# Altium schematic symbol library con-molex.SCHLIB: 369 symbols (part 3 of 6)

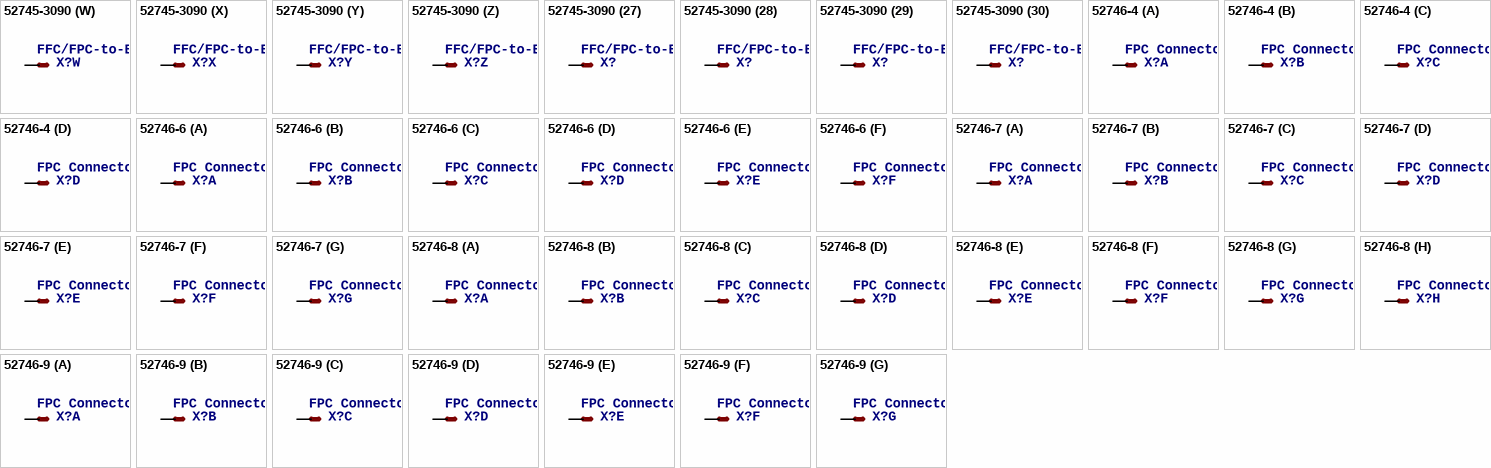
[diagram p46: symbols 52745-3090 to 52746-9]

## 52745-3090
designator X?, comment FFC/FPC-to-Board  0.50mm (.020") SMT Top Contact   Right Angle, ZIF, Style Receptacle 52745 / 52435 Source: http://www.molex.com/product/ffc/52745.html
footprint 52745-3090
part A pins: 1 S
part B pins: 2 S
part C pins: 3 S
part D pins: 4 S
part E pins: 5 S
part F pins: 6 S
part G pins: 7 S
part H pins: 8 S
part I pins: 9 S
part J pins: 10 S
part K pins: 11 S
part L pins: 12 S
part M pins: 13 S
part N pins: 14 S
part O pins: 15 S
part P pins: 16 S
part Q pins: 17 S
part R pins: 18 S
part S pins: 19 S
part T pins: 20 S
part U pins: 21 S
part V pins: 22 S
part W pins: 23 S
part X pins: 24 S
part Y pins: 25 S
part Z pins: 26 S
part 27 pins: 27 S
part 28 pins: 28 S
part 29 pins: 29 S
part 30 pins: 30 S

## 52746-4
designator X?, comment FPC Connector ZIF for SMT 0.5mm   Source: http://www.farnell.com/datasheets/73044.pdf [DWG. NO. (Sheet 1 OF 2) SD-52746-**17]
MPN: 52746-442
footprint 52746-4
part A pins: 1 S
part B pins: 2 S
part C pins: 3 S
part D pins: 4 S

## 52746-6
designator X?, comment FPC Connector ZIF for SMT 0.5mm   Source: http://www.farnell.com/datasheets/73044.pdf [DWG. NO. (Sheet 1 OF 2) SD-52746-**17]
footprint 52746-6
part A pins: 1 S
part B pins: 2 S
part C pins: 3 S
part D pins: 4 S
part E pins: 5 S
part F pins: 6 S

## 52746-7
designator X?, comment FPC Connector ZIF for SMT 0.5mm   Source: http://www.farnell.com/datasheets/73044.pdf [DWG. NO. (Sheet 1 OF 2) SD-52746-**17]
footprint 52746-7
part A pins: 1 S
part B pins: 2 S
part C pins: 3 S
part D pins: 4 S
part E pins: 5 S
part F pins: 6 S
part G pins: 7 S

## 52746-8
designator X?, comment FPC Connector ZIF for SMT 0.5mm   Source: http://www.farnell.com/datasheets/73044.pdf [DWG. NO. (Sheet 1 OF 2) SD-52746-**17]
footprint 52746-8
part A pins: 1 S
part B pins: 2 S
part C pins: 3 S
part D pins: 4 S
part E pins: 5 S
part F pins: 6 S
part G pins: 7 S
part H pins: 8 S

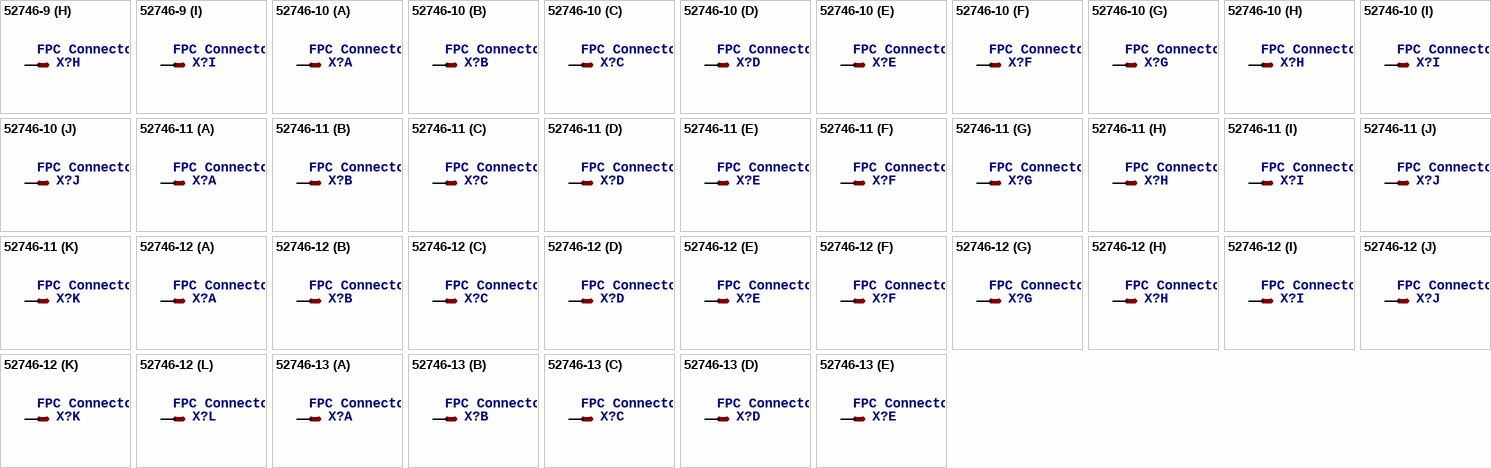
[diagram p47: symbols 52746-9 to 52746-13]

## 52746-9
designator X?, comment FPC Connector ZIF for SMT 0.5mm   Source: http://www.farnell.com/datasheets/73044.pdf [DWG. NO. (Sheet 1 OF 2) SD-52746-**17]
footprint 52746-9
part A pins: 1 S
part B pins: 2 S
part C pins: 3 S
part D pins: 4 S
part E pins: 5 S
part F pins: 6 S
part G pins: 7 S
part H pins: 8 S
part I pins: 9 S

## 52746-10
designator X?, comment FPC Connector ZIF for SMT 0.5mm   Source: http://www.farnell.com/datasheets/73044.pdf [DWG. NO. (Sheet 1 OF 2) SD-52746-**17]
footprint 52746-10
part A pins: 1 S
part B pins: 2 S
part C pins: 3 S
part D pins: 4 S
part E pins: 5 S
part F pins: 6 S
part G pins: 7 S
part H pins: 8 S
part I pins: 9 S
part J pins: 10 S

## 52746-11
designator X?, comment FPC Connector ZIF for SMT 0.5mm   Source: http://www.farnell.com/datasheets/73044.pdf [DWG. NO. (Sheet 1 OF 2) SD-52746-**17]
footprint 52746-11
part A pins: 1 S
part B pins: 2 S
part C pins: 3 S
part D pins: 4 S
part E pins: 5 S
part F pins: 6 S
part G pins: 7 S
part H pins: 8 S
part I pins: 9 S
part J pins: 10 S
part K pins: 11 S

## 52746-12
designator X?, comment FPC Connector ZIF for SMT 0.5mm   Source: http://www.farnell.com/datasheets/73044.pdf [DWG. NO. (Sheet 1 OF 2) SD-52746-**17]
footprint 52746-12
part A pins: 1 S
part B pins: 2 S
part C pins: 3 S
part D pins: 4 S
part E pins: 5 S
part F pins: 6 S
part G pins: 7 S
part H pins: 8 S
part I pins: 9 S
part J pins: 10 S
part K pins: 11 S
part L pins: 12 S

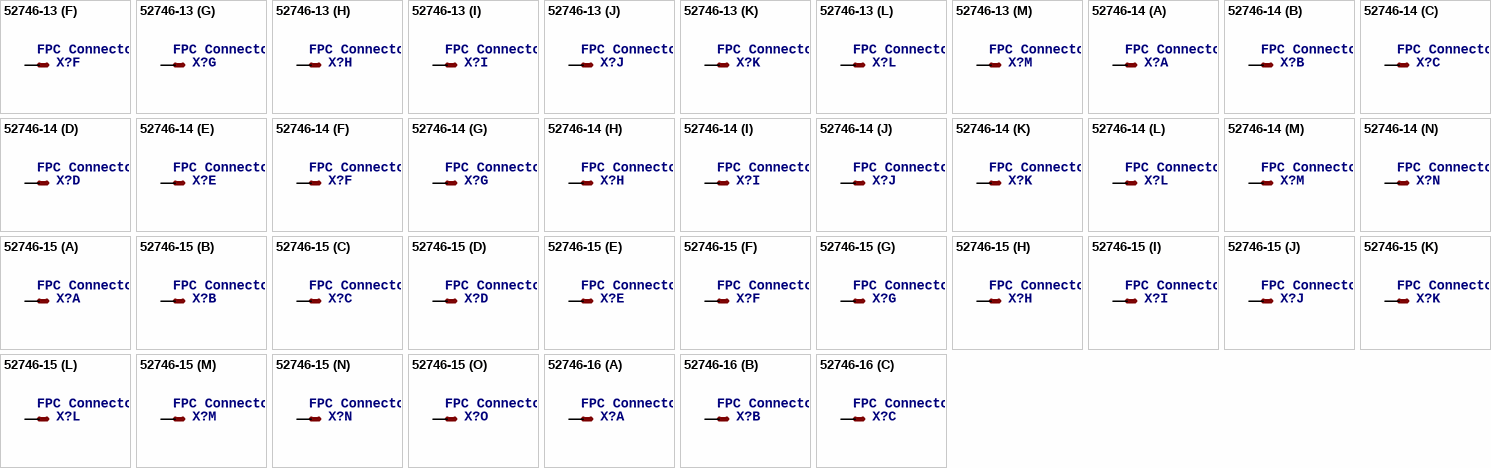
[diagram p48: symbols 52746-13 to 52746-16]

## 52746-13
designator X?, comment FPC Connector ZIF for SMT 0.5mm   Source: http://www.farnell.com/datasheets/73044.pdf [DWG. NO. (Sheet 1 OF 2) SD-52746-**17]
footprint 52746-13
part A pins: 1 S
part B pins: 2 S
part C pins: 3 S
part D pins: 4 S
part E pins: 5 S
part F pins: 6 S
part G pins: 7 S
part H pins: 8 S
part I pins: 9 S
part J pins: 10 S
part K pins: 11 S
part L pins: 12 S
part M pins: 13 S

## 52746-14
designator X?, comment FPC Connector ZIF for SMT 0.5mm   Source: http://www.farnell.com/datasheets/73044.pdf [DWG. NO. (Sheet 1 OF 2) SD-52746-**17]
footprint 52746-14
part A pins: 1 S
part B pins: 2 S
part C pins: 3 S
part D pins: 4 S
part E pins: 5 S
part F pins: 6 S
part G pins: 7 S
part H pins: 8 S
part I pins: 9 S
part J pins: 10 S
part K pins: 11 S
part L pins: 12 S
part M pins: 13 S
part N pins: 14 S

## 52746-15
designator X?, comment FPC Connector ZIF for SMT 0.5mm   Source: http://www.farnell.com/datasheets/73044.pdf [DWG. NO. (Sheet 1 OF 2) SD-52746-**17]
footprint 52746-15
part A pins: 1 S
part B pins: 2 S
part C pins: 3 S
part D pins: 4 S
part E pins: 5 S
part F pins: 6 S
part G pins: 7 S
part H pins: 8 S
part I pins: 9 S
part J pins: 10 S
part K pins: 11 S
part L pins: 12 S
part M pins: 13 S
part N pins: 14 S
part O pins: 15 S

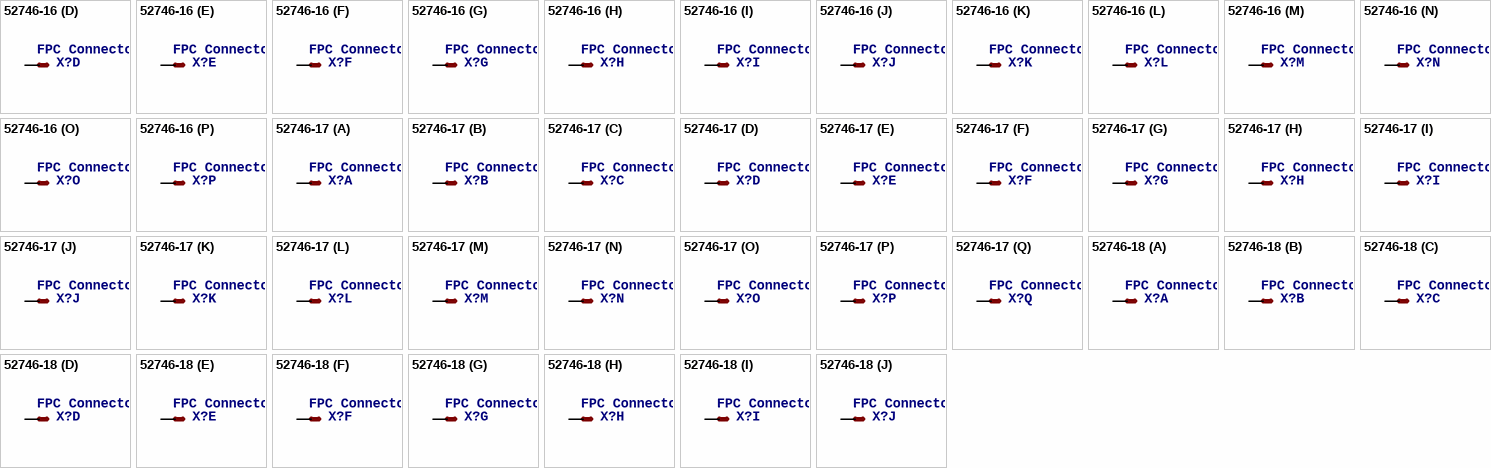
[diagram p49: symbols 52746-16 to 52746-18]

## 52746-16
designator X?, comment FPC Connector ZIF for SMT 0.5mm   Source: http://www.farnell.com/datasheets/73044.pdf [DWG. NO. (Sheet 1 OF 2) SD-52746-**17]
footprint 52746-16
part A pins: 1 S
part B pins: 2 S
part C pins: 3 S
part D pins: 4 S
part E pins: 5 S
part F pins: 6 S
part G pins: 7 S
part H pins: 8 S
part I pins: 9 S
part J pins: 10 S
part K pins: 11 S
part L pins: 12 S
part M pins: 13 S
part N pins: 14 S
part O pins: 15 S
part P pins: 16 S

## 52746-17
designator X?, comment FPC Connector ZIF for SMT 0.5mm   Source: http://www.farnell.com/datasheets/73044.pdf [DWG. NO. (Sheet 1 OF 2) SD-52746-**17]
MPN: 52746-1770
footprint 52746-17
part A pins: 1 S
part B pins: 2 S
part C pins: 3 S
part D pins: 4 S
part E pins: 5 S
part F pins: 6 S
part G pins: 7 S
part H pins: 8 S
part I pins: 9 S
part J pins: 10 S
part K pins: 11 S
part L pins: 12 S
part M pins: 13 S
part N pins: 14 S
part O pins: 15 S
part P pins: 16 S
part Q pins: 17 S

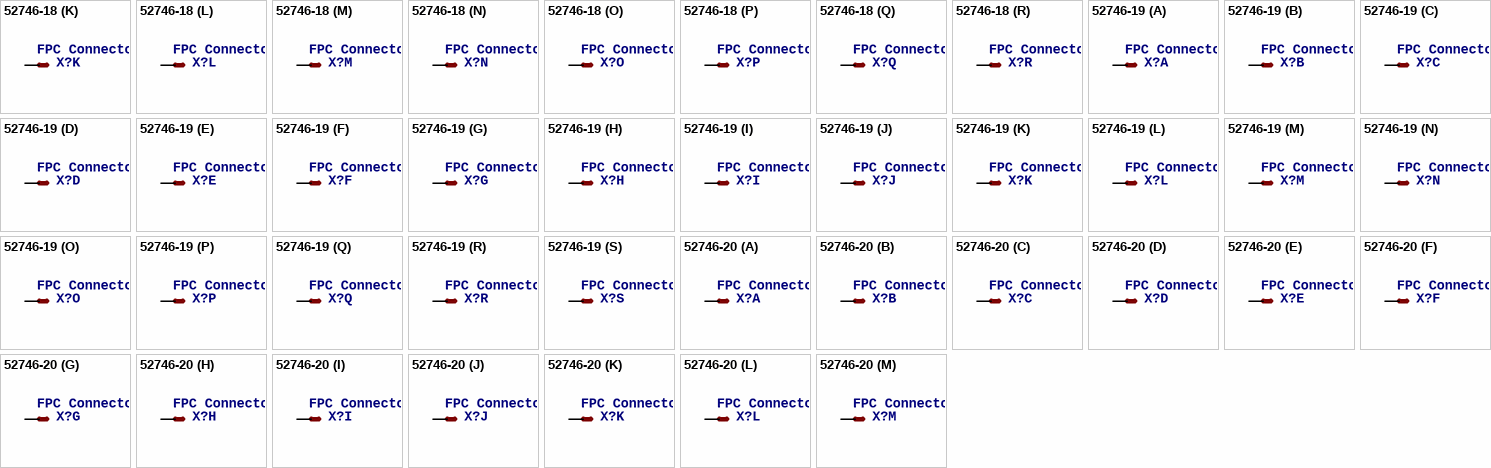
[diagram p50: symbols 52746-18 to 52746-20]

## 52746-18
designator X?, comment FPC Connector ZIF for SMT 0.5mm   Source: http://www.farnell.com/datasheets/73044.pdf [DWG. NO. (Sheet 1 OF 2) SD-52746-**17]
MPN: 52746-1870
footprint 52746-18
part A pins: 1 S
part B pins: 2 S
part C pins: 3 S
part D pins: 4 S
part E pins: 5 S
part F pins: 6 S
part G pins: 7 S
part H pins: 8 S
part I pins: 9 S
part J pins: 10 S
part K pins: 11 S
part L pins: 12 S
part M pins: 13 S
part N pins: 14 S
part O pins: 15 S
part P pins: 16 S
part Q pins: 17 S
part R pins: 18 S

## 52746-19
designator X?, comment FPC Connector ZIF for SMT 0.5mm   Source: http://www.farnell.com/datasheets/73044.pdf [DWG. NO. (Sheet 1 OF 2) SD-52746-**17]
MPN: 52746-1970
footprint 52746-19
part A pins: 1 S
part B pins: 2 S
part C pins: 3 S
part D pins: 4 S
part E pins: 5 S
part F pins: 6 S
part G pins: 7 S
part H pins: 8 S
part I pins: 9 S
part J pins: 10 S
part K pins: 11 S
part L pins: 12 S
part M pins: 13 S
part N pins: 14 S
part O pins: 15 S
part P pins: 16 S
part Q pins: 17 S
part R pins: 18 S
part S pins: 19 S

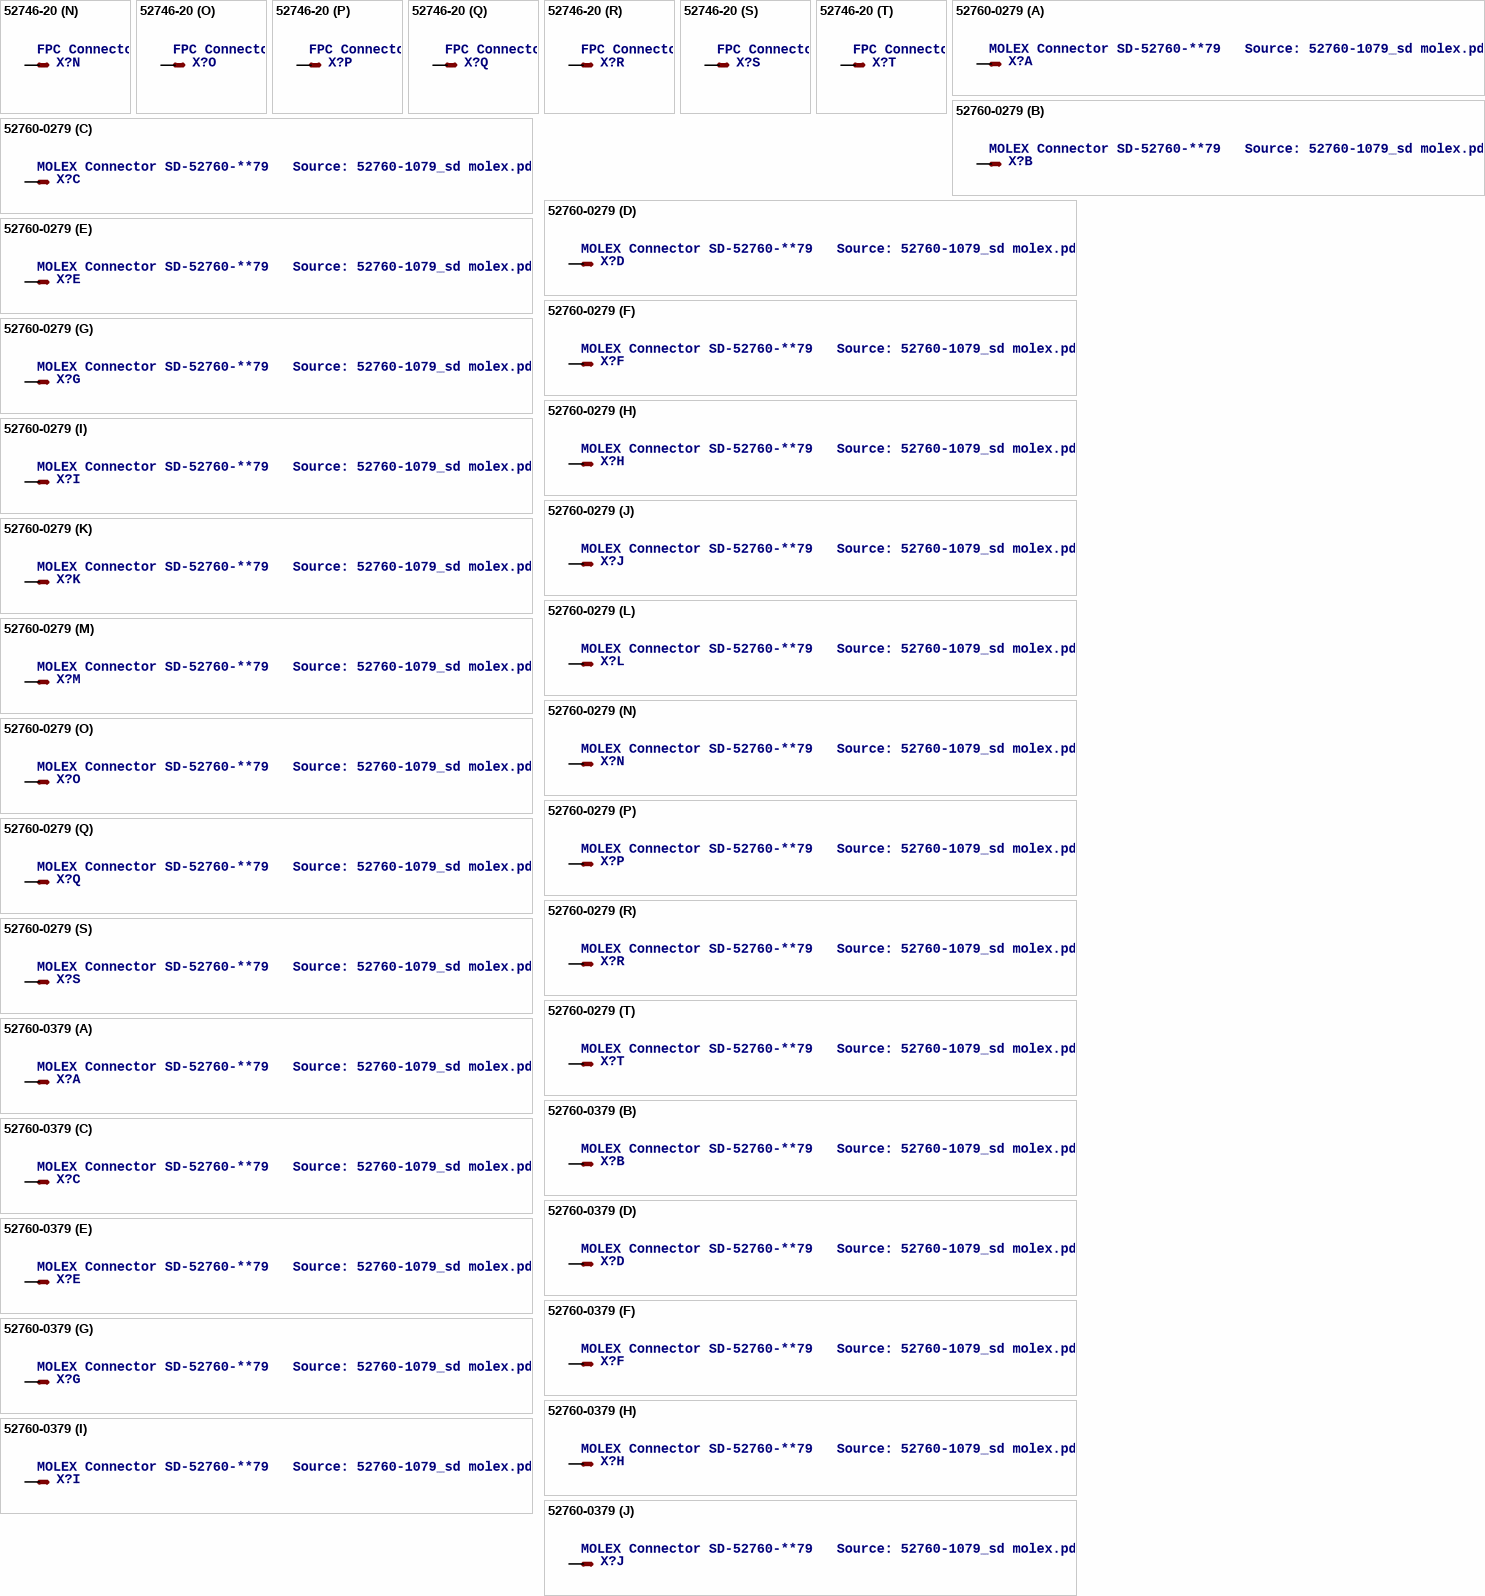
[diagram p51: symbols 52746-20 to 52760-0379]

## 52746-20
designator X?, comment FPC Connector ZIF for SMT 0.5mm   Source: http://www.farnell.com/datasheets/73044.pdf [DWG. NO. (Sheet 1 OF 2) SD-52746-**17] Distributor: Farnell 9786350
footprint 52746-20
part A pins: 1 S
part B pins: 2 S
part C pins: 3 S
part D pins: 4 S
part E pins: 5 S
part F pins: 6 S
part G pins: 7 S
part H pins: 8 S
part I pins: 9 S
part J pins: 10 S
part K pins: 11 S
part L pins: 12 S
part M pins: 13 S
part N pins: 14 S
part O pins: 15 S
part P pins: 16 S
part Q pins: 17 S
part R pins: 18 S
part S pins: 19 S
part T pins: 20 S

## 52760-0279
designator X?, comment MOLEX Connector SD-52760-**79   Source: 52760-1079_sd molex.pdf
MPN: 52760-0279
footprint 52760-0279
part A pins: 1 S
part B pins: 2 S
part C pins: 3 S
part D pins: 4 S
part E pins: 5 S
part F pins: 6 S
part G pins: 7 S
part H pins: 8 S
part I pins: 9 S
part J pins: 10 S
part K pins: 11 S
part L pins: 12 S
part M pins: 13 S
part N pins: 14 S
part O pins: 15 S
part P pins: 16 S
part Q pins: 17 S
part R pins: 18 S
part S pins: 19 S
part T pins: 20 S

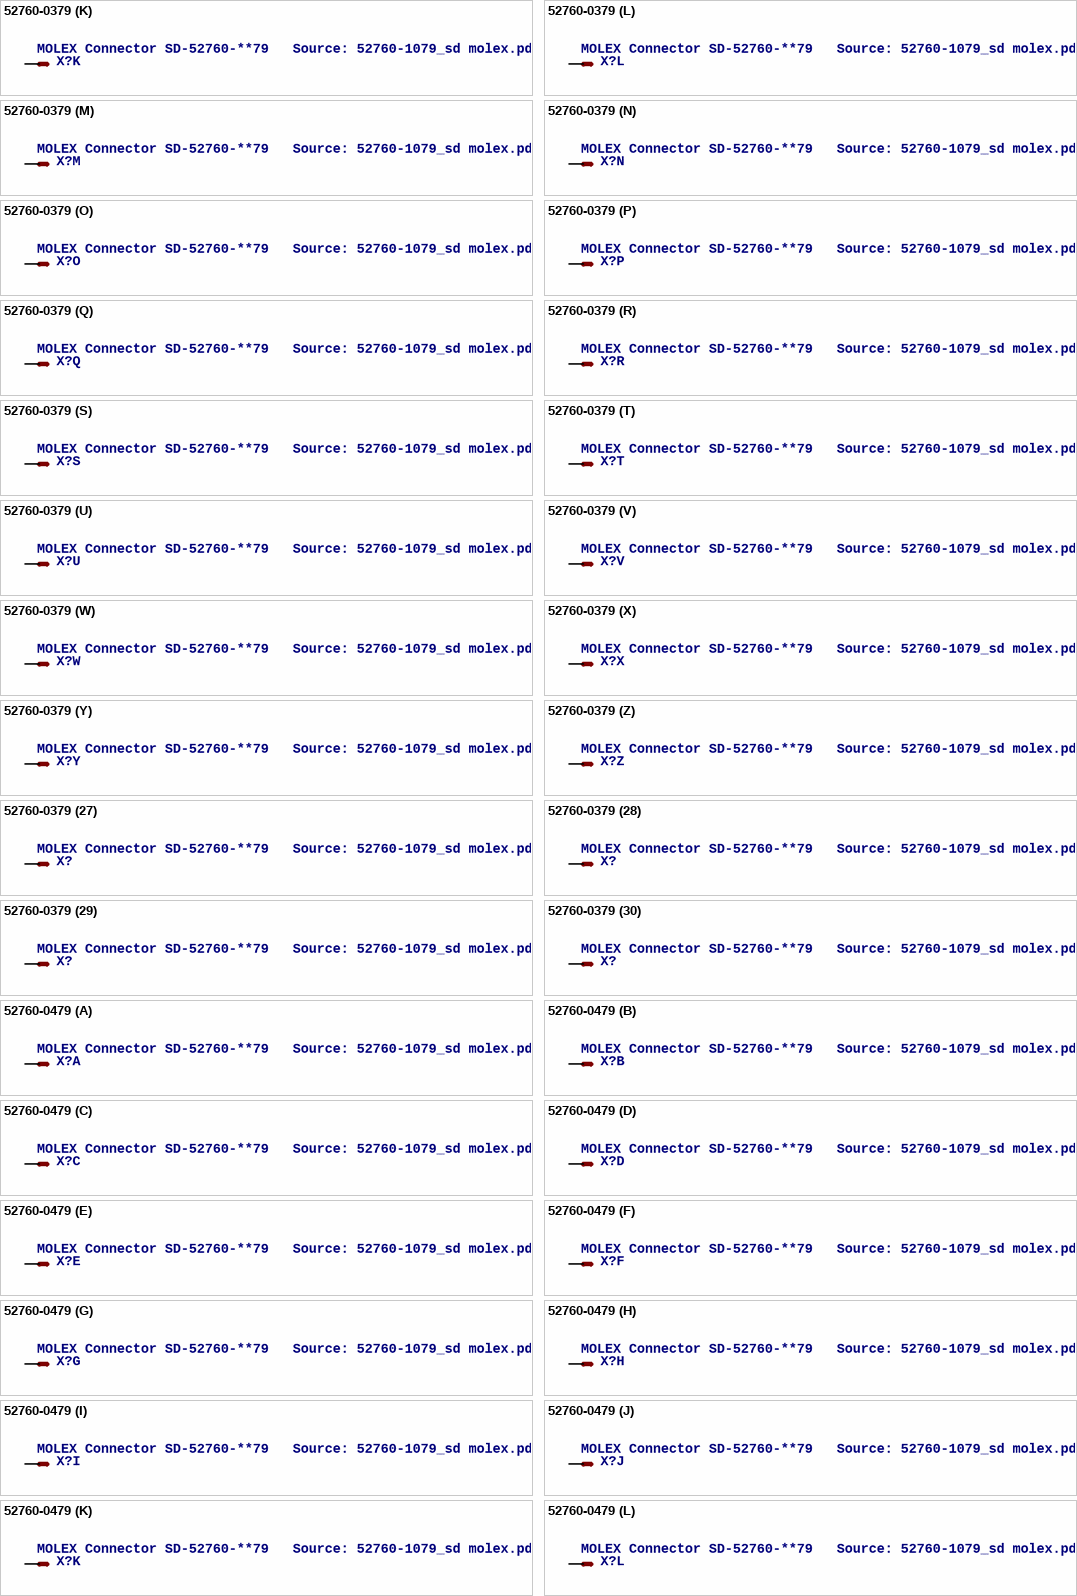
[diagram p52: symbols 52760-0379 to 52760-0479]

## 52760-0379
designator X?, comment MOLEX Connector SD-52760-**79   Source: 52760-1079_sd molex.pdf
MPN: 52760-0379
footprint 52760-0379
part A pins: 1 S
part B pins: 2 S
part C pins: 3 S
part D pins: 4 S
part E pins: 5 S
part F pins: 6 S
part G pins: 7 S
part H pins: 8 S
part I pins: 9 S
part J pins: 10 S
part K pins: 11 S
part L pins: 12 S
part M pins: 13 S
part N pins: 14 S
part O pins: 15 S
part P pins: 16 S
part Q pins: 17 S
part R pins: 18 S
part S pins: 19 S
part T pins: 20 S
part U pins: 21 S
part V pins: 22 S
part W pins: 23 S
part X pins: 24 S
part Y pins: 25 S
part Z pins: 26 S
part 27 pins: 27 S
part 28 pins: 28 S
part 29 pins: 29 S
part 30 pins: 30 S

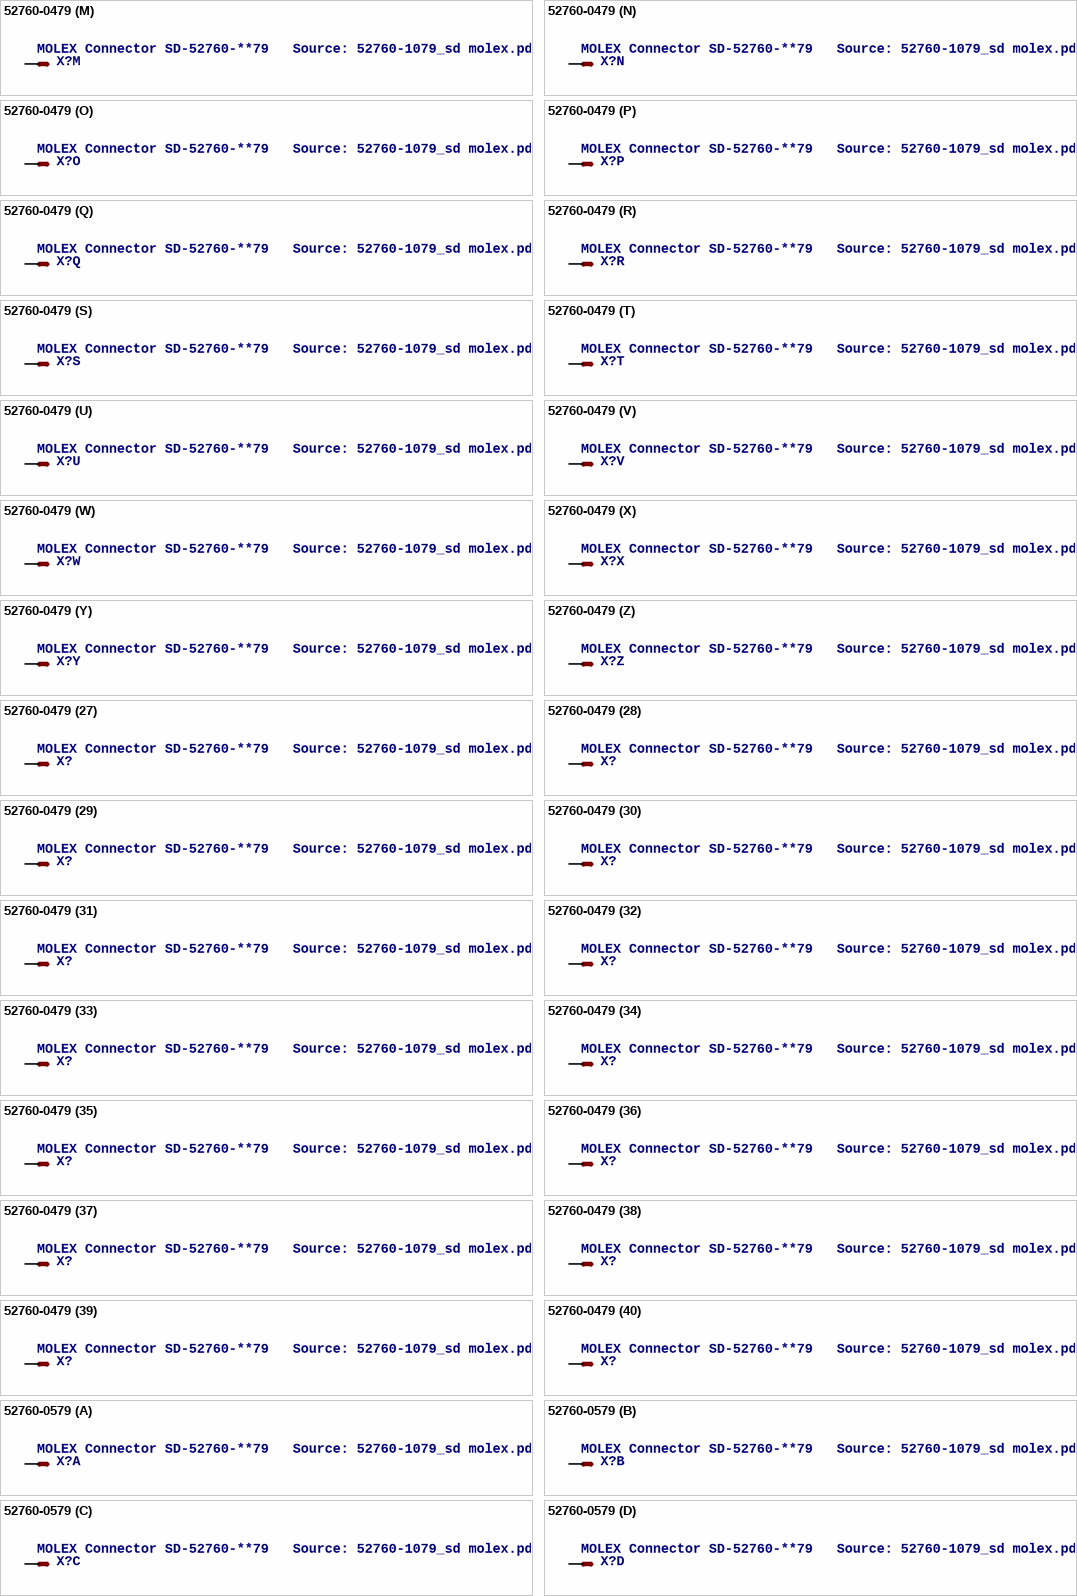
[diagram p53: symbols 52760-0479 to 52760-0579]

## 52760-0479
designator X?, comment MOLEX Connector SD-52760-**79   Source: 52760-1079_sd molex.pdf
footprint 52760-0479
part A pins: 1 S
part B pins: 2 S
part C pins: 3 S
part D pins: 4 S
part E pins: 5 S
part F pins: 6 S
part G pins: 7 S
part H pins: 8 S
part I pins: 9 S
part J pins: 10 S
part K pins: 11 S
part L pins: 12 S
part M pins: 13 S
part N pins: 14 S
part O pins: 15 S
part P pins: 16 S
part Q pins: 17 S
part R pins: 18 S
part S pins: 19 S
part T pins: 20 S
part U pins: 21 S
part V pins: 22 S
part W pins: 23 S
part X pins: 24 S
part Y pins: 25 S
part Z pins: 26 S
part 27 pins: 27 S
part 28 pins: 28 S
part 29 pins: 29 S
part 30 pins: 30 S
part 31 pins: 31 S
part 32 pins: 32 S
part 33 pins: 33 S
part 34 pins: 34 S
part 35 pins: 35 S
part 36 pins: 36 S
part 37 pins: 37 S
part 38 pins: 38 S
part 39 pins: 39 S
part 40 pins: 40 S

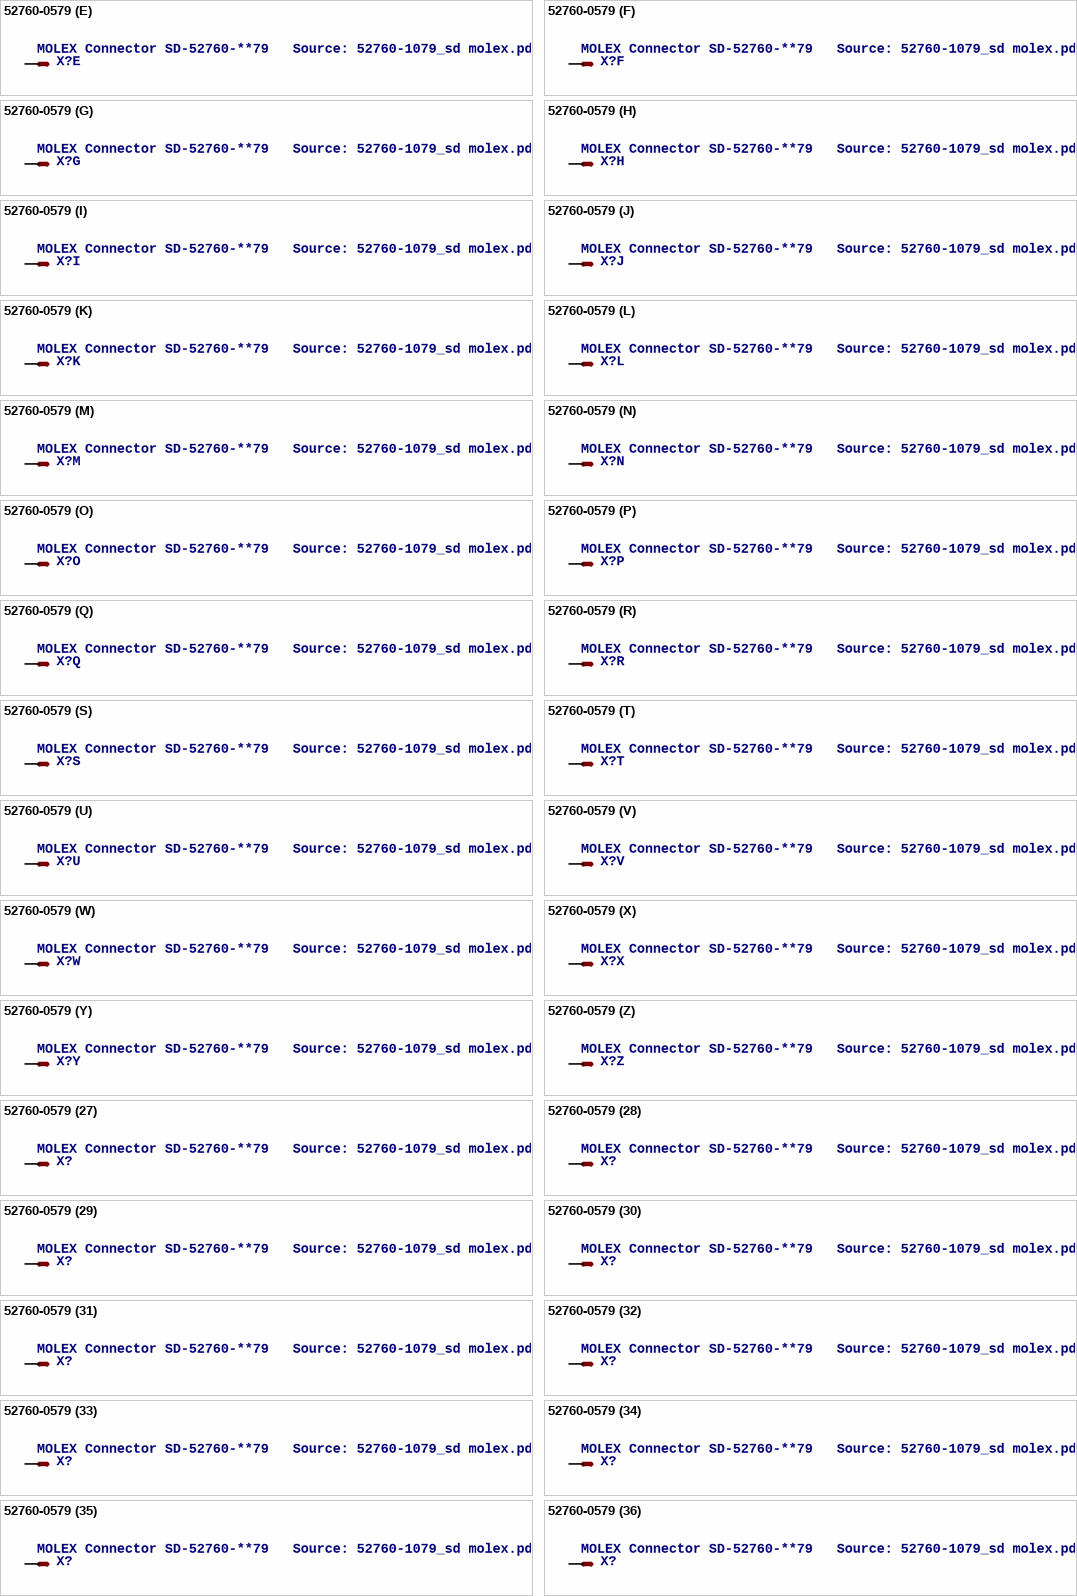
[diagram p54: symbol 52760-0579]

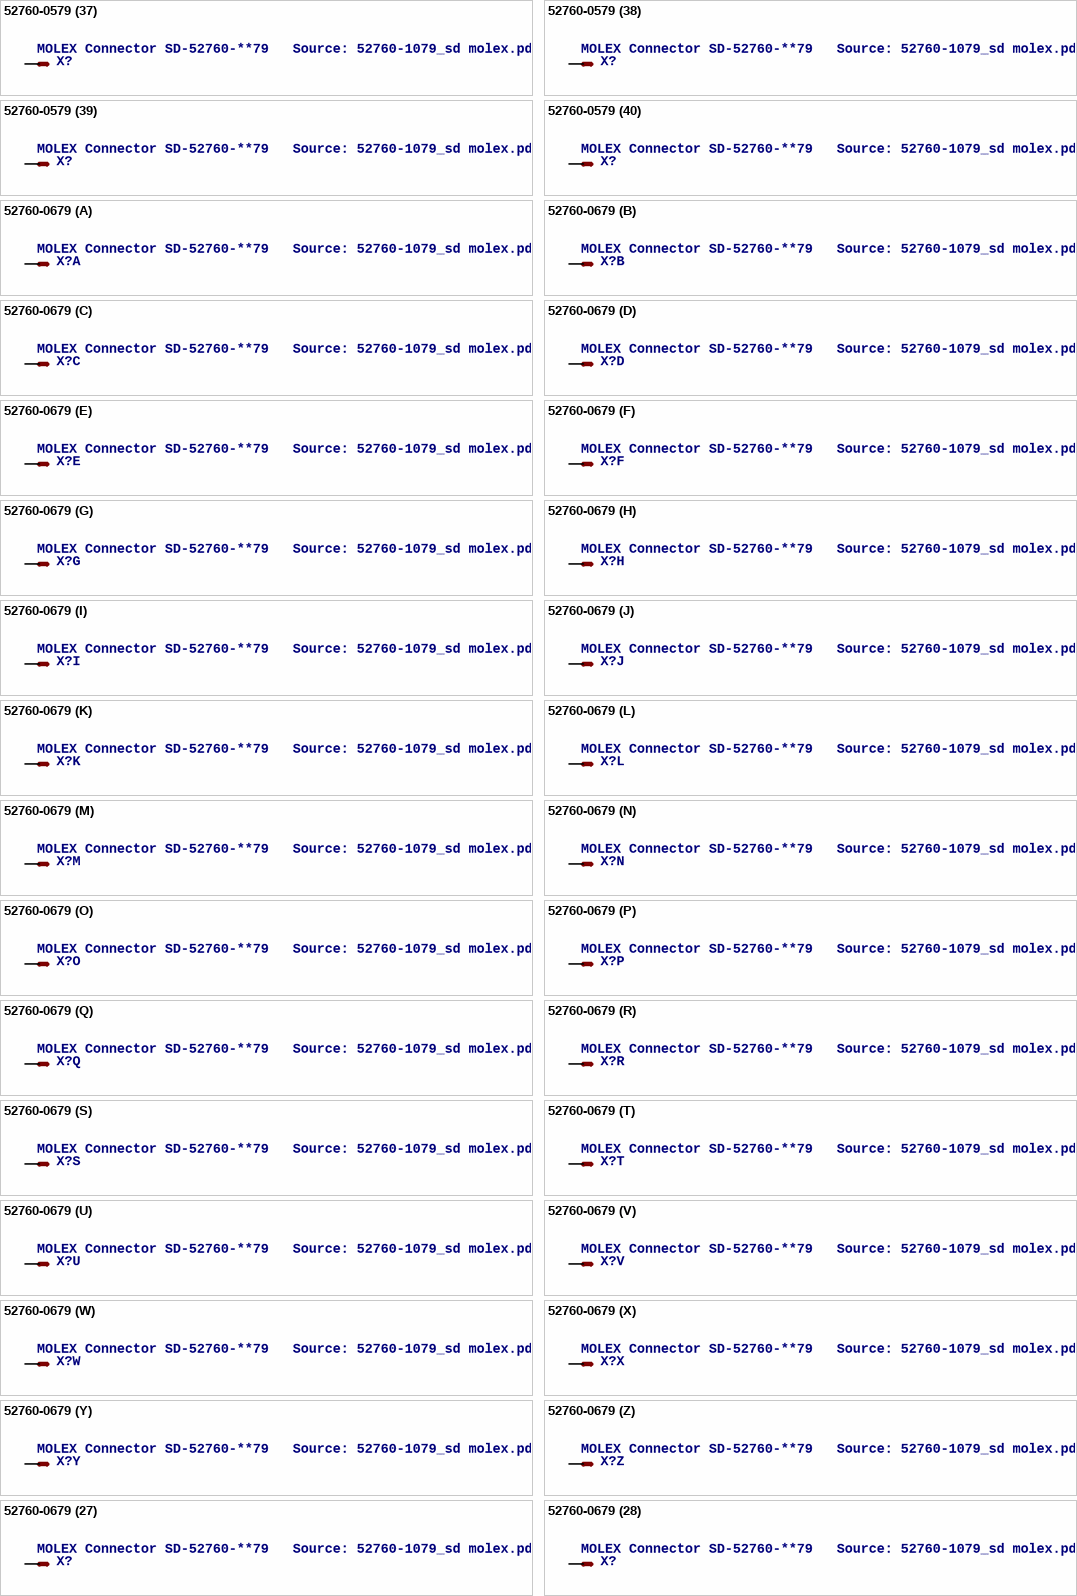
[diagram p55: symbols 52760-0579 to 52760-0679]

## 52760-0579
designator X?, comment MOLEX Connector SD-52760-**79   Source: 52760-1079_sd molex.pdf
footprint 52760-0579
part A pins: 1 S
part B pins: 2 S
part C pins: 3 S
part D pins: 4 S
part E pins: 5 S
part F pins: 6 S
part G pins: 7 S
part H pins: 8 S
part I pins: 9 S
part J pins: 10 S
part K pins: 11 S
part L pins: 12 S
part M pins: 13 S
part N pins: 14 S
part O pins: 15 S
part P pins: 16 S
part Q pins: 17 S
part R pins: 18 S
part S pins: 19 S
part T pins: 20 S
part U pins: 21 S
part V pins: 22 S
part W pins: 23 S
part X pins: 24 S
part Y pins: 25 S
part Z pins: 26 S
part 27 pins: 27 S
part 28 pins: 28 S
part 29 pins: 29 S
part 30 pins: 30 S
part 31 pins: 31 S
part 32 pins: 32 S
part 33 pins: 33 S
part 34 pins: 34 S
part 35 pins: 35 S
part 36 pins: 36 S
part 37 pins: 37 S
part 38 pins: 38 S
part 39 pins: 39 S
part 40 pins: 40 S
part 41 pins: 41 S
part 42 pins: 42 S
part 43 pins: 43 S
part 44 pins: 44 S
part 45 pins: 45 S
part 46 pins: 46 S
part 47 pins: 47 S
part 48 pins: 48 S
part 49 pins: 49 S
part 50 pins: 50 S

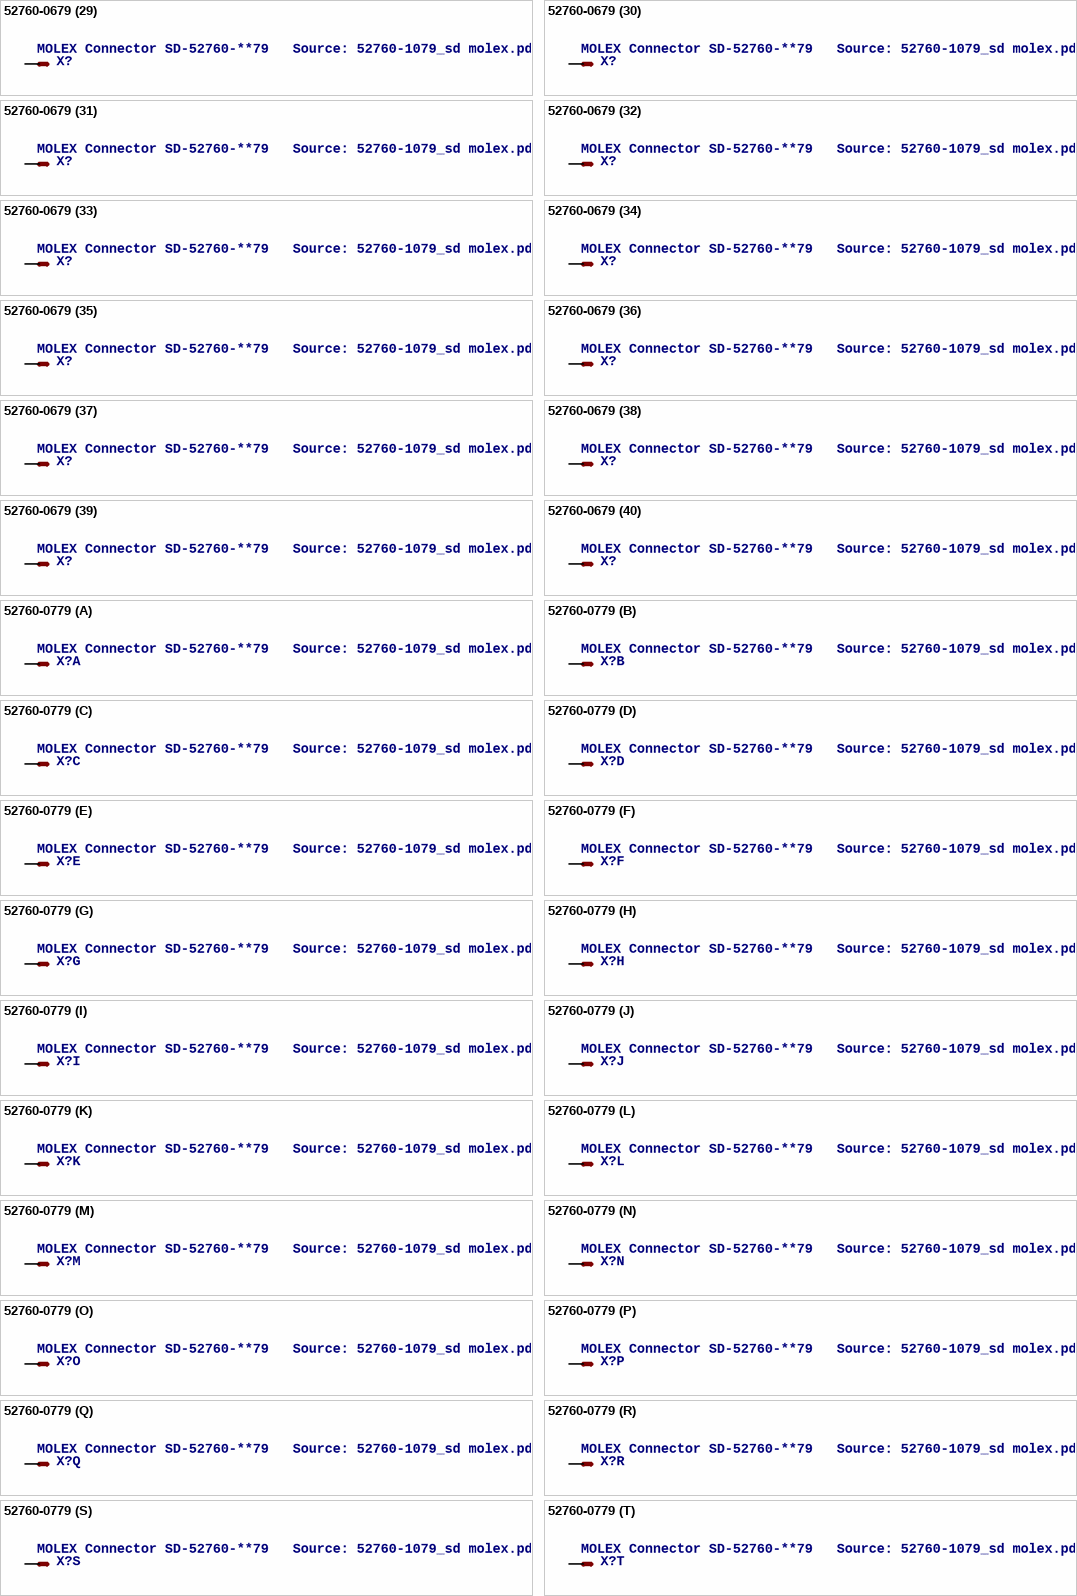
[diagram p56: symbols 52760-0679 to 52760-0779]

## 52760-0679
designator X?, comment MOLEX Connector SD-52760-**79   Source: 52760-1079_sd molex.pdf
footprint 52760-0679
part A pins: 1 S
part B pins: 2 S
part C pins: 3 S
part D pins: 4 S
part E pins: 5 S
part F pins: 6 S
part G pins: 7 S
part H pins: 8 S
part I pins: 9 S
part J pins: 10 S
part K pins: 11 S
part L pins: 12 S
part M pins: 13 S
part N pins: 14 S
part O pins: 15 S
part P pins: 16 S
part Q pins: 17 S
part R pins: 18 S
part S pins: 19 S
part T pins: 20 S
part U pins: 21 S
part V pins: 22 S
part W pins: 23 S
part X pins: 24 S
part Y pins: 25 S
part Z pins: 26 S
part 27 pins: 27 S
part 28 pins: 28 S
part 29 pins: 29 S
part 30 pins: 30 S
part 31 pins: 31 S
part 32 pins: 32 S
part 33 pins: 33 S
part 34 pins: 34 S
part 35 pins: 35 S
part 36 pins: 36 S
part 37 pins: 37 S
part 38 pins: 38 S
part 39 pins: 39 S
part 40 pins: 40 S
part 41 pins: 41 S
part 42 pins: 42 S
part 43 pins: 43 S
part 44 pins: 44 S
part 45 pins: 45 S
part 46 pins: 46 S
part 47 pins: 47 S
part 48 pins: 48 S
part 49 pins: 49 S
part 50 pins: 50 S
part 51 pins: 51 S
part 52 pins: 52 S
part 53 pins: 53 S
part 54 pins: 54 S
part 55 pins: 55 S
part 56 pins: 56 S
part 57 pins: 57 S
part 58 pins: 58 S
part 59 pins: 59 S
part 60 pins: 60 S

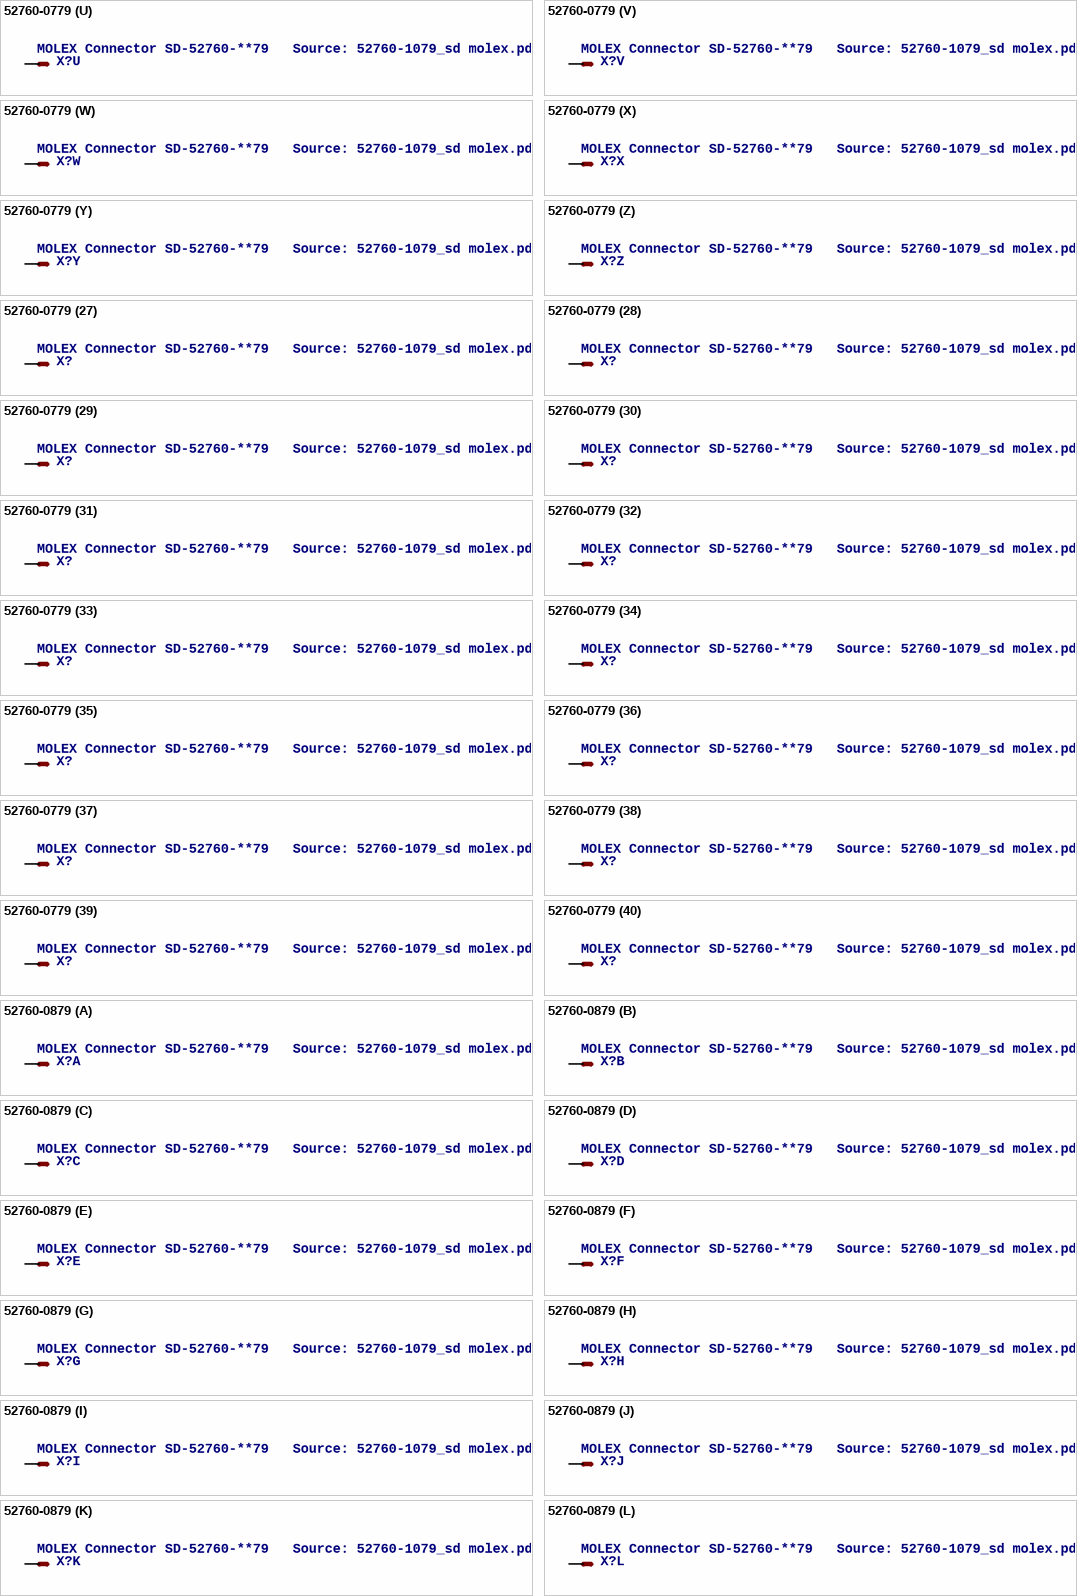
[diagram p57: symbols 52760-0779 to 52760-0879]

## 52760-0779
designator X?, comment MOLEX Connector SD-52760-**79   Source: 52760-1079_sd molex.pdf
footprint 52760-0779
part A pins: 1 S
part B pins: 2 S
part C pins: 3 S
part D pins: 4 S
part E pins: 5 S
part F pins: 6 S
part G pins: 7 S
part H pins: 8 S
part I pins: 9 S
part J pins: 10 S
part K pins: 11 S
part L pins: 12 S
part M pins: 13 S
part N pins: 14 S
part O pins: 15 S
part P pins: 16 S
part Q pins: 17 S
part R pins: 18 S
part S pins: 19 S
part T pins: 20 S
part U pins: 21 S
part V pins: 22 S
part W pins: 23 S
part X pins: 24 S
part Y pins: 25 S
part Z pins: 26 S
part 27 pins: 27 S
part 28 pins: 28 S
part 29 pins: 29 S
part 30 pins: 30 S
part 31 pins: 31 S
part 32 pins: 32 S
part 33 pins: 33 S
part 34 pins: 34 S
part 35 pins: 35 S
part 36 pins: 36 S
part 37 pins: 37 S
part 38 pins: 38 S
part 39 pins: 39 S
part 40 pins: 40 S
part 41 pins: 41 S
part 42 pins: 42 S
part 43 pins: 43 S
part 44 pins: 44 S
part 45 pins: 45 S
part 46 pins: 46 S
part 47 pins: 47 S
part 48 pins: 48 S
part 49 pins: 49 S
part 50 pins: 50 S
part 51 pins: 51 S
part 52 pins: 52 S
part 53 pins: 53 S
part 54 pins: 54 S
part 55 pins: 55 S
part 56 pins: 56 S
part 57 pins: 57 S
part 58 pins: 58 S
part 59 pins: 59 S
part 60 pins: 60 S
part 61 pins: 61 S
part 62 pins: 62 S
part 63 pins: 63 S
part 64 pins: 64 S
part 65 pins: 65 S
part 66 pins: 66 S
part 67 pins: 67 S
part 68 pins: 68 S
part 69 pins: 69 S
part 70 pins: 70 S

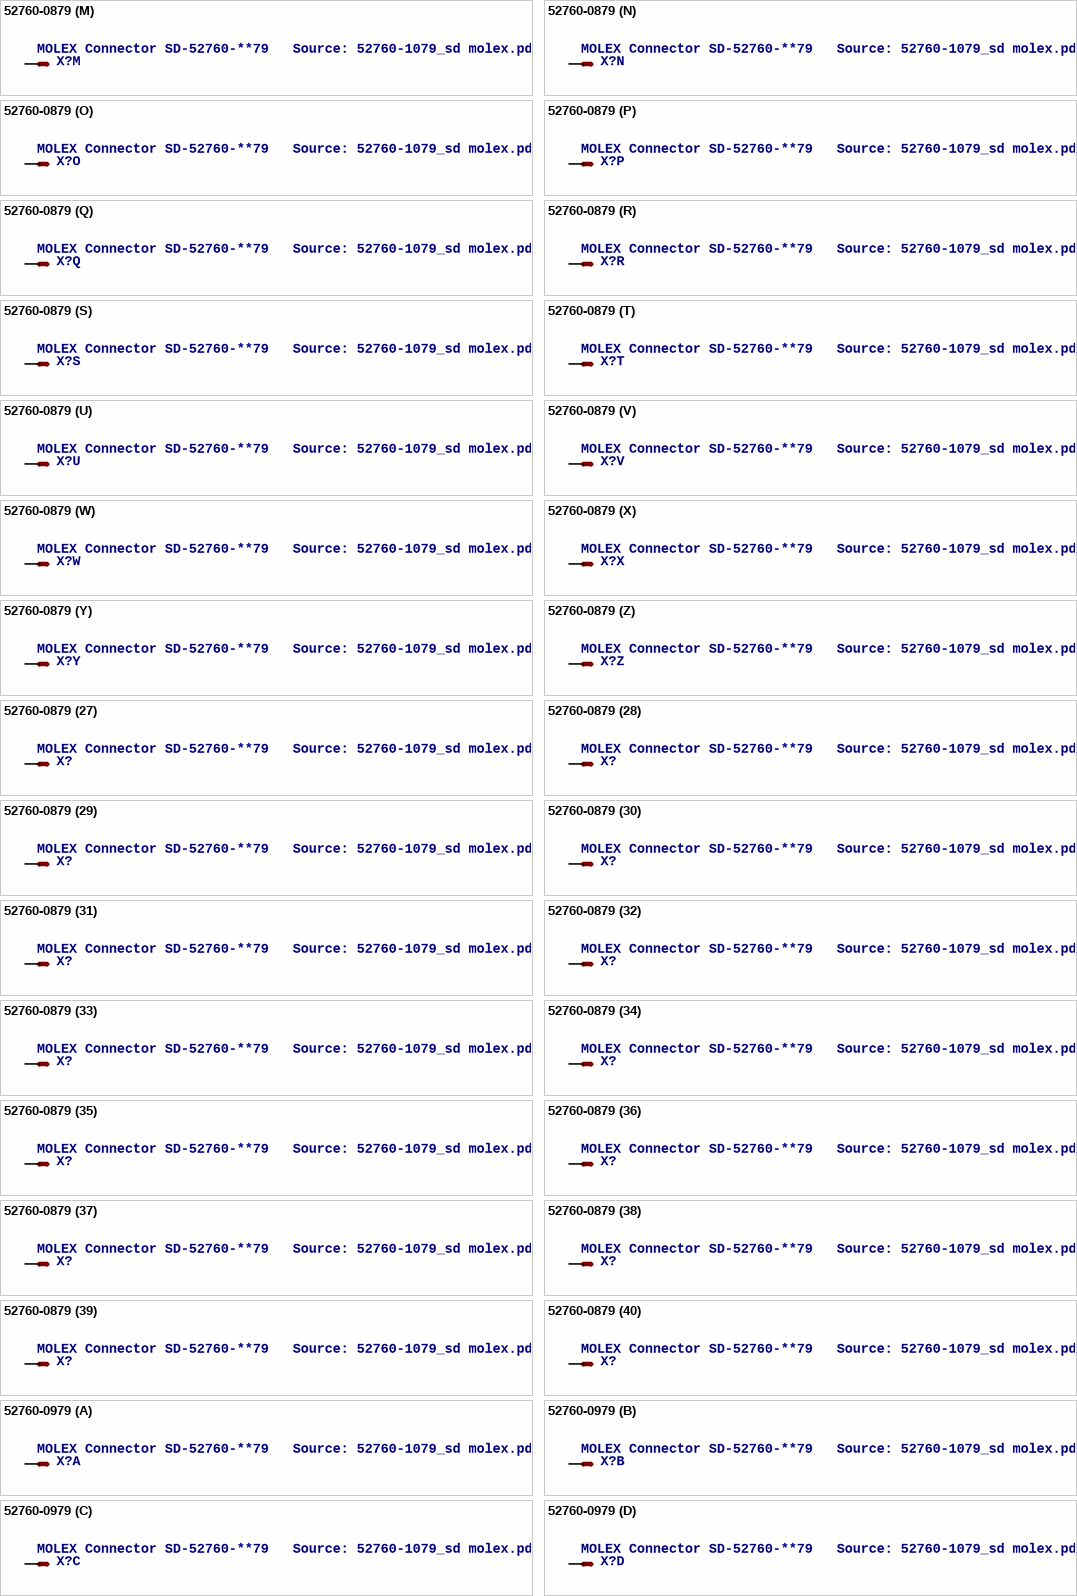
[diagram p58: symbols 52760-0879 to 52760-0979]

## 52760-0879
designator X?, comment MOLEX Connector SD-52760-**79   Source: 52760-1079_sd molex.pdf
footprint 52760-0879
part A pins: 1 S
part B pins: 2 S
part C pins: 3 S
part D pins: 4 S
part E pins: 5 S
part F pins: 6 S
part G pins: 7 S
part H pins: 8 S
part I pins: 9 S
part J pins: 10 S
part K pins: 11 S
part L pins: 12 S
part M pins: 13 S
part N pins: 14 S
part O pins: 15 S
part P pins: 16 S
part Q pins: 17 S
part R pins: 18 S
part S pins: 19 S
part T pins: 20 S
part U pins: 21 S
part V pins: 22 S
part W pins: 23 S
part X pins: 24 S
part Y pins: 25 S
part Z pins: 26 S
part 27 pins: 27 S
part 28 pins: 28 S
part 29 pins: 29 S
part 30 pins: 30 S
part 31 pins: 31 S
part 32 pins: 32 S
part 33 pins: 33 S
part 34 pins: 34 S
part 35 pins: 35 S
part 36 pins: 36 S
part 37 pins: 37 S
part 38 pins: 38 S
part 39 pins: 39 S
part 40 pins: 40 S
part 41 pins: 41 S
part 42 pins: 42 S
part 43 pins: 43 S
part 44 pins: 44 S
part 45 pins: 45 S
part 46 pins: 46 S
part 47 pins: 47 S
part 48 pins: 48 S
part 49 pins: 49 S
part 50 pins: 50 S
part 51 pins: 51 S
part 52 pins: 52 S
part 53 pins: 53 S
part 54 pins: 54 S
part 55 pins: 55 S
part 56 pins: 56 S
part 57 pins: 57 S
part 58 pins: 58 S
part 59 pins: 59 S
part 60 pins: 60 S
part 61 pins: 61 S
part 62 pins: 62 S
part 63 pins: 63 S
part 64 pins: 64 S
part 65 pins: 65 S
part 66 pins: 66 S
part 67 pins: 67 S
part 68 pins: 68 S
part 69 pins: 69 S
part 70 pins: 70 S
part 71 pins: 71 S
part 72 pins: 72 S
part 73 pins: 73 S
part 74 pins: 74 S
part 75 pins: 75 S
part 76 pins: 76 S
part 77 pins: 77 S
part 78 pins: 78 S
part 79 pins: 79 S
part 80 pins: 80 S

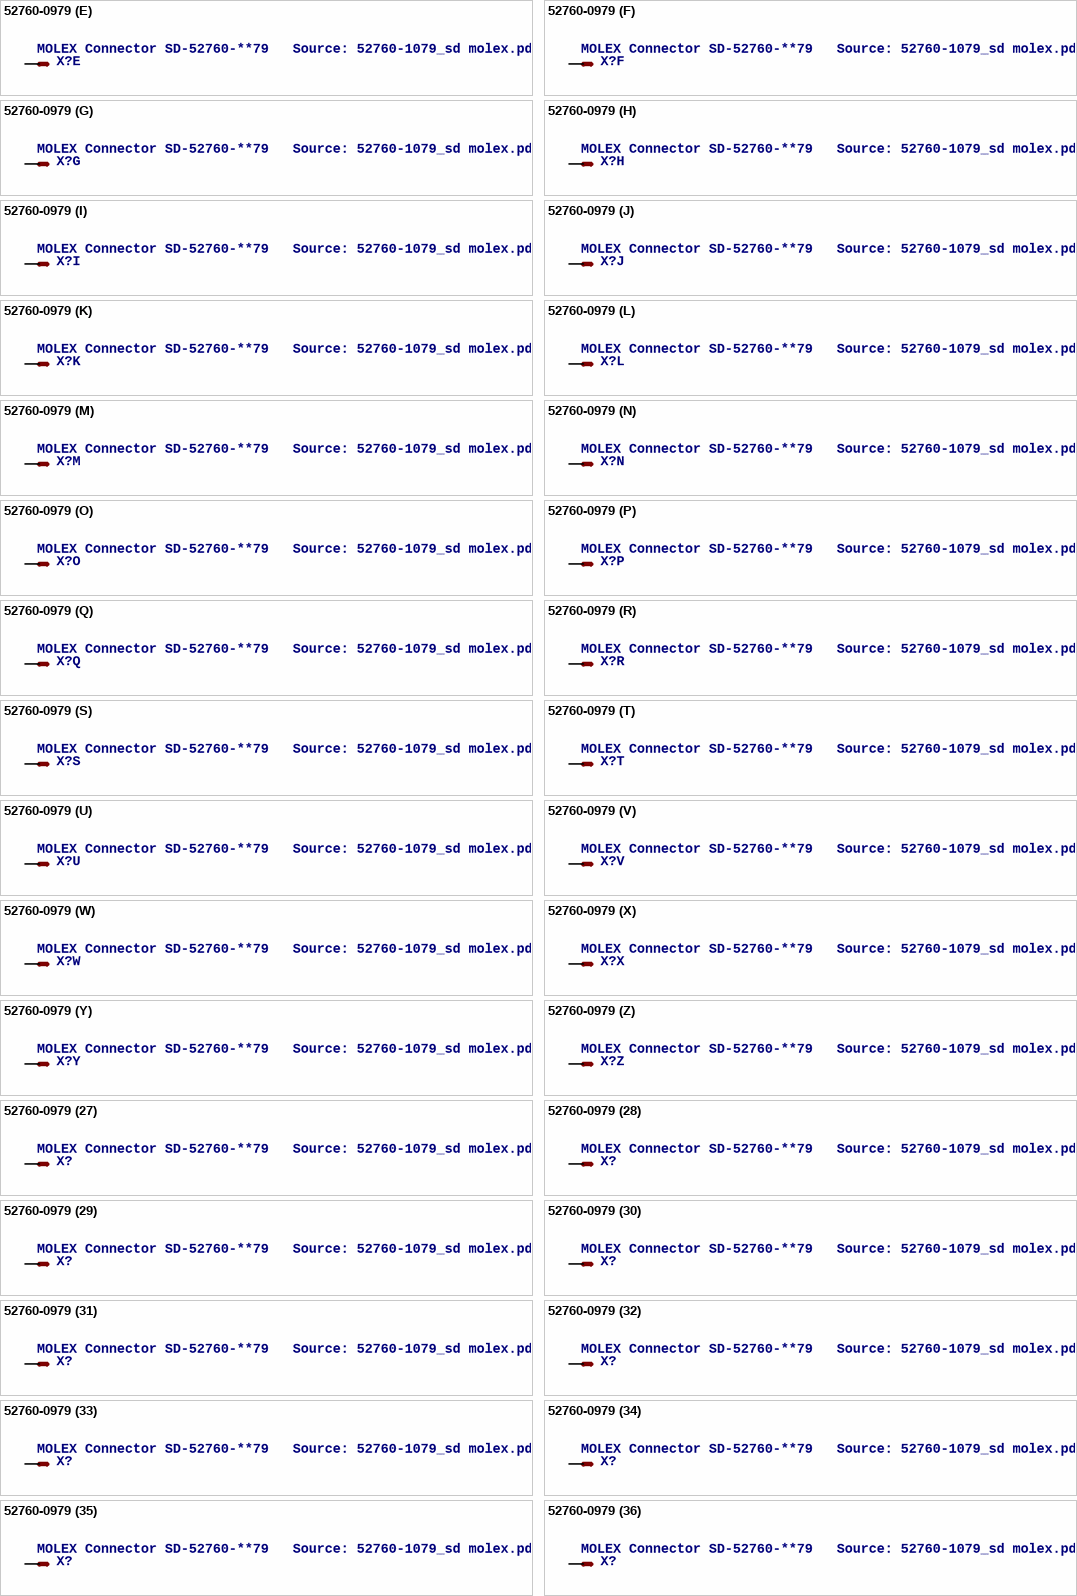
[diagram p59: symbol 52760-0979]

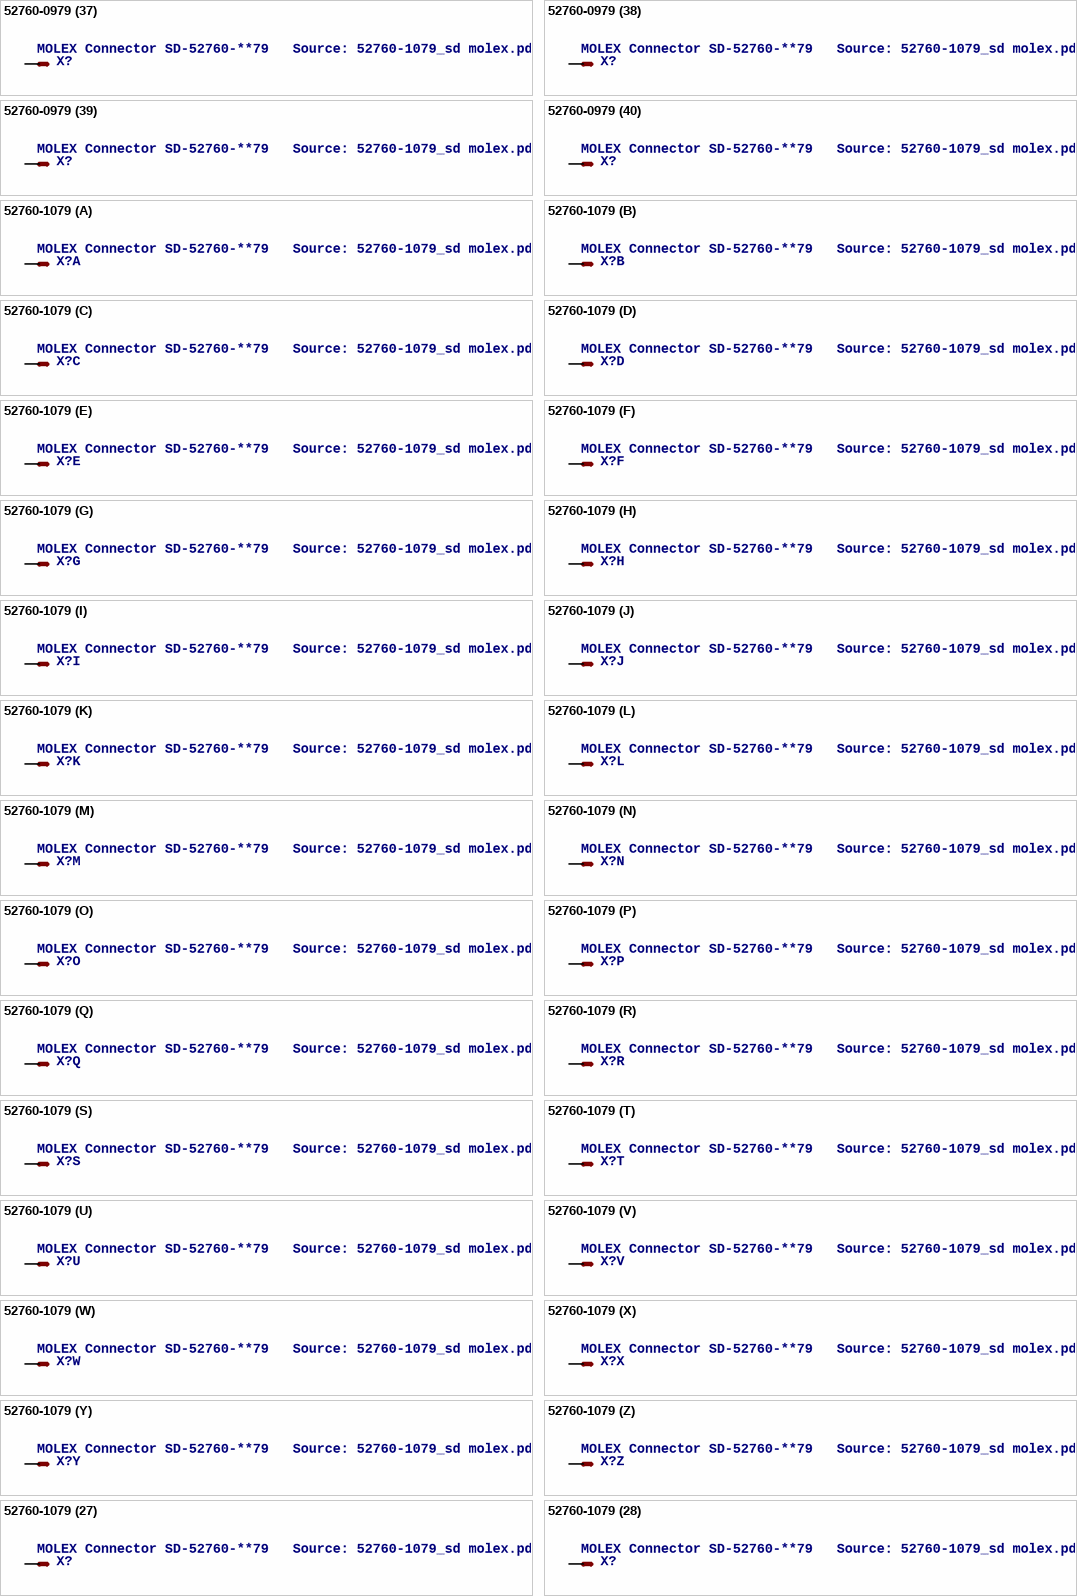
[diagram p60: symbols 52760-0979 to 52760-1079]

## 52760-0979
designator X?, comment MOLEX Connector SD-52760-**79   Source: 52760-1079_sd molex.pdf
MPN: 52760-0979
footprint 52760-0979
part A pins: 1 S
part B pins: 2 S
part C pins: 3 S
part D pins: 4 S
part E pins: 5 S
part F pins: 6 S
part G pins: 7 S
part H pins: 8 S
part I pins: 9 S
part J pins: 10 S
part K pins: 11 S
part L pins: 12 S
part M pins: 13 S
part N pins: 14 S
part O pins: 15 S
part P pins: 16 S
part Q pins: 17 S
part R pins: 18 S
part S pins: 19 S
part T pins: 20 S
part U pins: 21 S
part V pins: 22 S
part W pins: 23 S
part X pins: 24 S
part Y pins: 25 S
part Z pins: 26 S
part 27 pins: 27 S
part 28 pins: 28 S
part 29 pins: 29 S
part 30 pins: 30 S
part 31 pins: 31 S
part 32 pins: 32 S
part 33 pins: 33 S
part 34 pins: 34 S
part 35 pins: 35 S
part 36 pins: 36 S
part 37 pins: 37 S
part 38 pins: 38 S
part 39 pins: 39 S
part 40 pins: 40 S
part 41 pins: 41 S
part 42 pins: 42 S
part 43 pins: 43 S
part 44 pins: 44 S
part 45 pins: 45 S
part 46 pins: 46 S
part 47 pins: 47 S
part 48 pins: 48 S
part 49 pins: 49 S
part 50 pins: 50 S
part 51 pins: 51 S
part 52 pins: 52 S
part 53 pins: 53 S
part 54 pins: 54 S
part 55 pins: 55 S
part 56 pins: 56 S
part 57 pins: 57 S
part 58 pins: 58 S
part 59 pins: 59 S
part 60 pins: 60 S
part 61 pins: 61 S
part 62 pins: 62 S
part 63 pins: 63 S
part 64 pins: 64 S
part 65 pins: 65 S
part 66 pins: 66 S
part 67 pins: 67 S
part 68 pins: 68 S
part 69 pins: 69 S
part 70 pins: 70 S
part 71 pins: 71 S
part 72 pins: 72 S
part 73 pins: 73 S
part 74 pins: 74 S
part 75 pins: 75 S
part 76 pins: 76 S
part 77 pins: 77 S
part 78 pins: 78 S
part 79 pins: 79 S
part 80 pins: 80 S
part 81 pins: 81 S
part 82 pins: 82 S
part 83 pins: 83 S
part 84 pins: 84 S
part 85 pins: 85 S
part 86 pins: 86 S
part 87 pins: 87 S
part 88 pins: 88 S
part 89 pins: 89 S
part 90 pins: 90 S

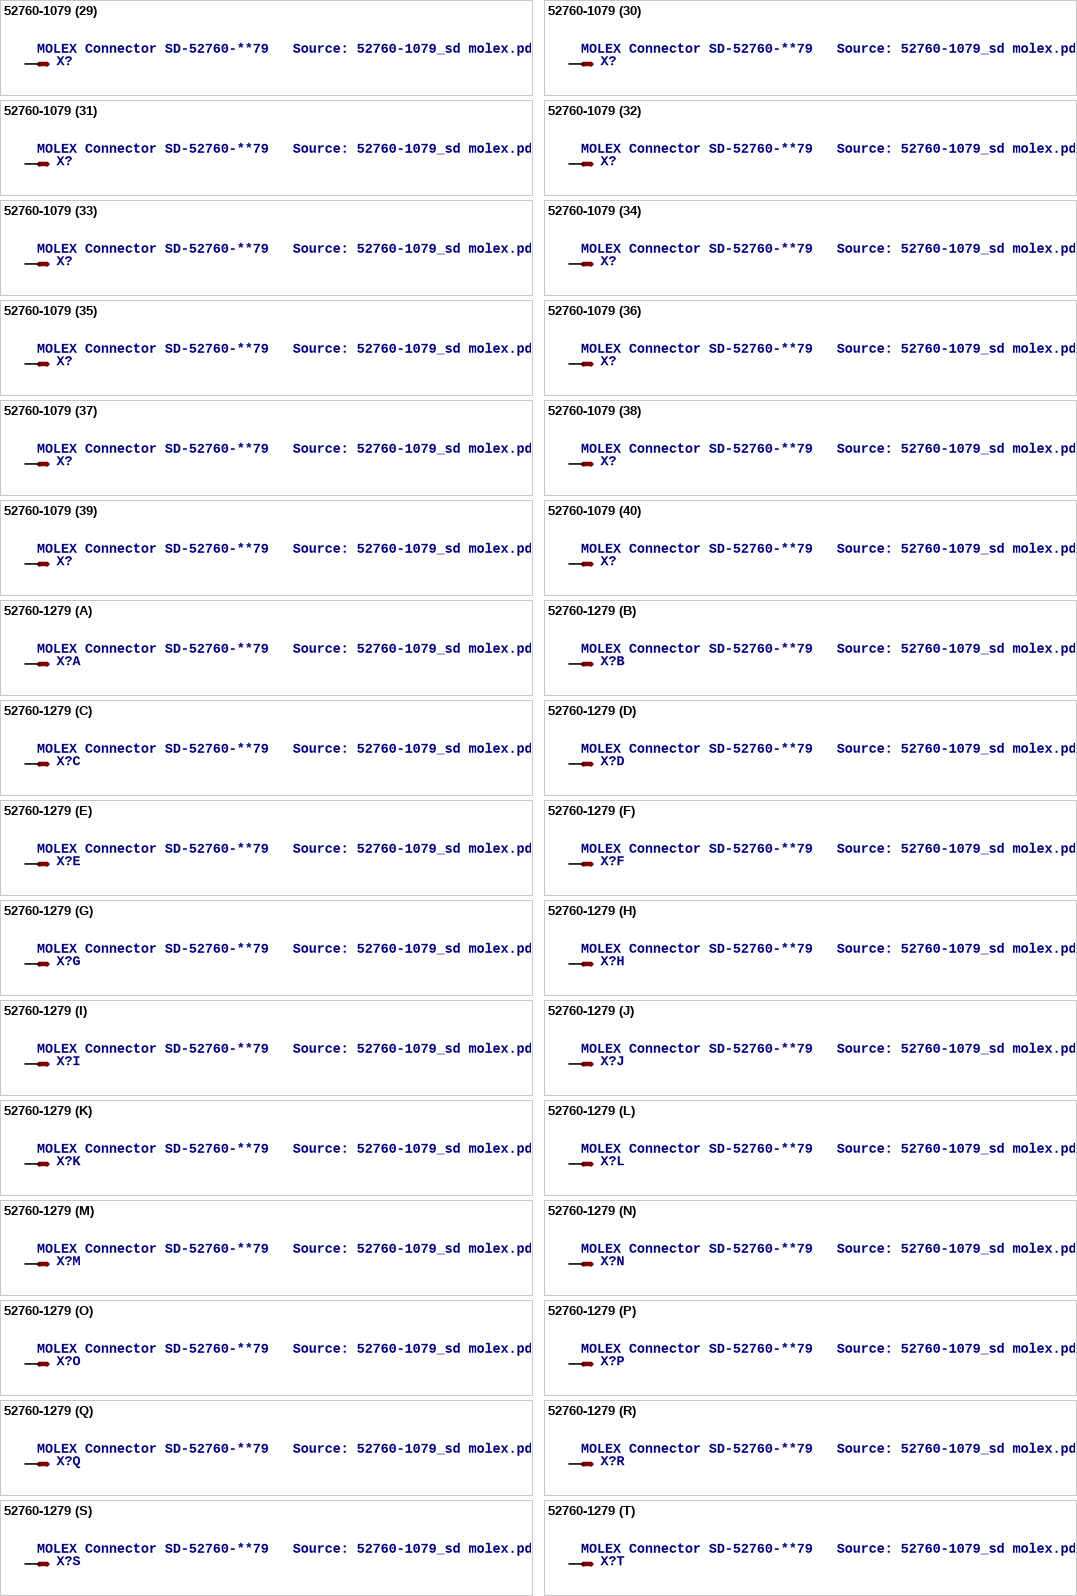
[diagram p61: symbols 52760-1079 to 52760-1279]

## 52760-1079
designator X?, comment MOLEX Connector SD-52760-**79   Source: 52760-1079_sd molex.pdf
footprint 52760-1079
part A pins: 1 S
part B pins: 2 S
part C pins: 3 S
part D pins: 4 S
part E pins: 5 S
part F pins: 6 S
part G pins: 7 S
part H pins: 8 S
part I pins: 9 S
part J pins: 10 S
part K pins: 11 S
part L pins: 12 S
part M pins: 13 S
part N pins: 14 S
part O pins: 15 S
part P pins: 16 S
part Q pins: 17 S
part R pins: 18 S
part S pins: 19 S
part T pins: 20 S
part U pins: 21 S
part V pins: 22 S
part W pins: 23 S
part X pins: 24 S
part Y pins: 25 S
part Z pins: 26 S
part 27 pins: 27 S
part 28 pins: 28 S
part 29 pins: 29 S
part 30 pins: 30 S
part 31 pins: 31 S
part 32 pins: 32 S
part 33 pins: 33 S
part 34 pins: 34 S
part 35 pins: 35 S
part 36 pins: 36 S
part 37 pins: 37 S
part 38 pins: 38 S
part 39 pins: 39 S
part 40 pins: 40 S
part 41 pins: 41 S
part 42 pins: 42 S
part 43 pins: 43 S
part 44 pins: 44 S
part 45 pins: 45 S
part 46 pins: 46 S
part 47 pins: 47 S
part 48 pins: 48 S
part 49 pins: 49 S
part 50 pins: 50 S
part 51 pins: 51 S
part 52 pins: 52 S
part 53 pins: 53 S
part 54 pins: 54 S
part 55 pins: 55 S
part 56 pins: 56 S
part 57 pins: 57 S
part 58 pins: 58 S
part 59 pins: 59 S
part 60 pins: 60 S
part 61 pins: 61 S
part 62 pins: 62 S
part 63 pins: 63 S
part 64 pins: 64 S
part 65 pins: 65 S
part 66 pins: 66 S
part 67 pins: 67 S
part 68 pins: 68 S
part 69 pins: 69 S
part 70 pins: 70 S
part 71 pins: 71 S
part 72 pins: 72 S
part 73 pins: 73 S
part 74 pins: 74 S
part 75 pins: 75 S
part 76 pins: 76 S
part 77 pins: 77 S
part 78 pins: 78 S
part 79 pins: 79 S
part 80 pins: 80 S
part 81 pins: 81 S
part 82 pins: 82 S
part 83 pins: 83 S
part 84 pins: 84 S
part 85 pins: 85 S
part 86 pins: 86 S
part 87 pins: 87 S
part 88 pins: 88 S
part 89 pins: 89 S
part 90 pins: 90 S
part 91 pins: 91 S
part 92 pins: 92 S
part 93 pins: 93 S
part 94 pins: 94 S
part 95 pins: 95 S
part 96 pins: 96 S
part 97 pins: 97 S
part 98 pins: 98 S
part 99 pins: 99 S
part 100 pins: 100 S

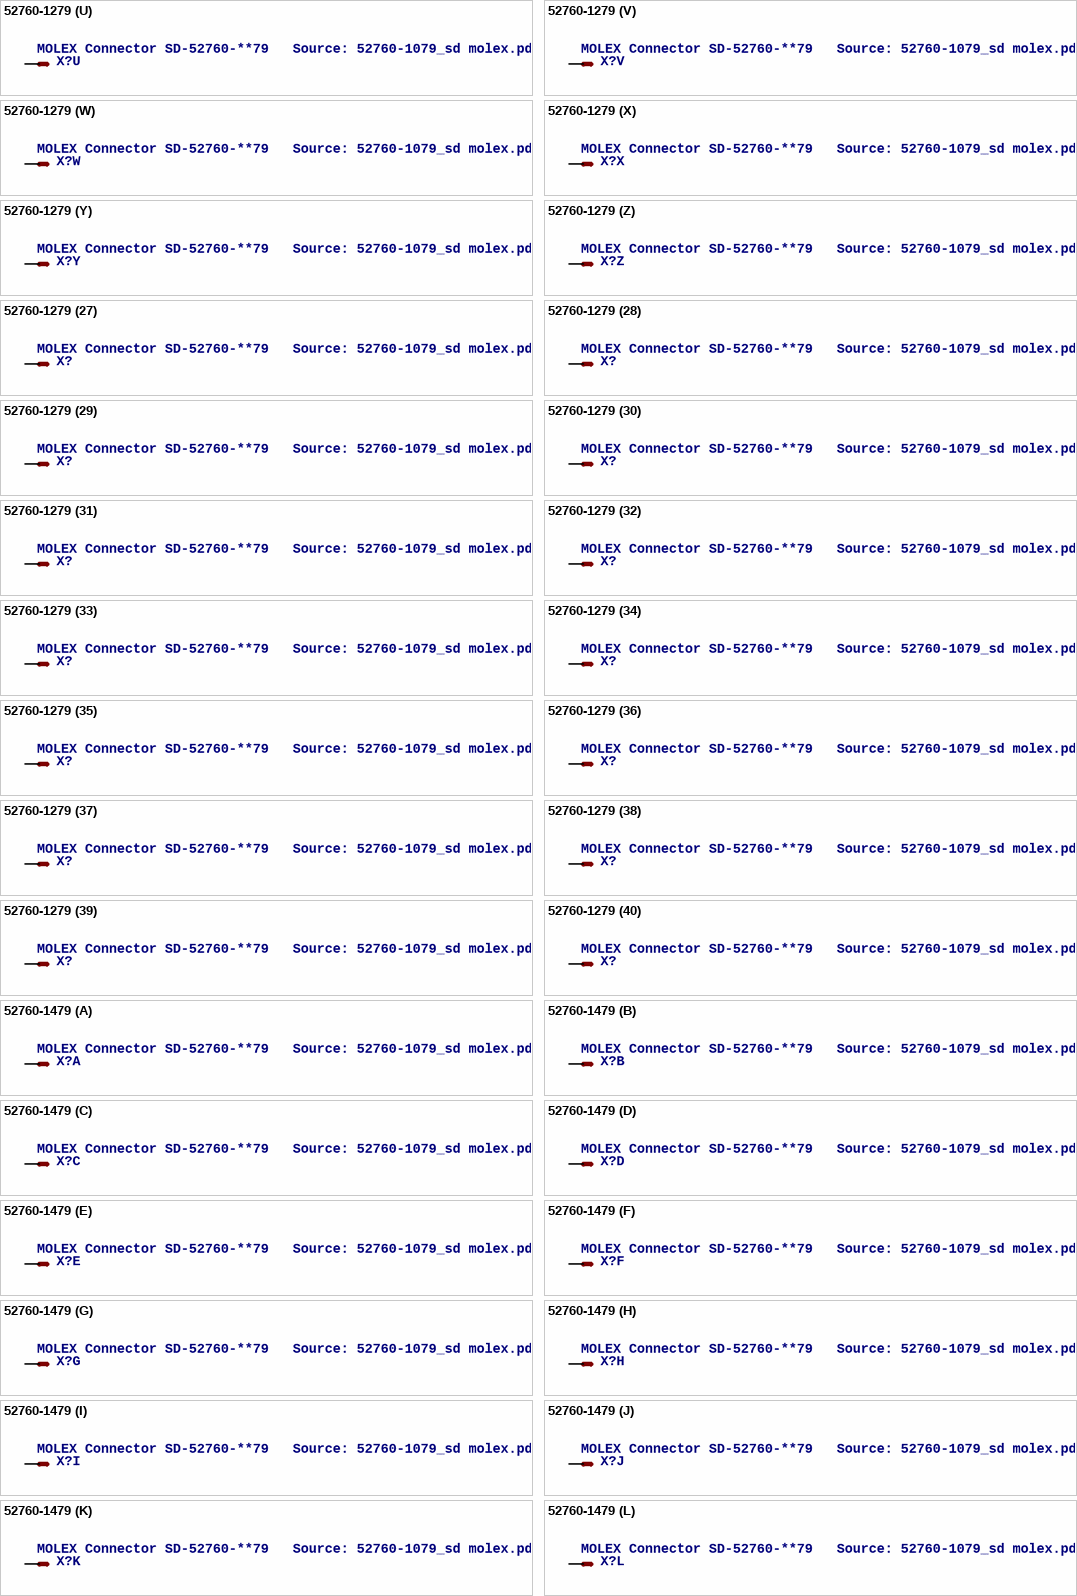
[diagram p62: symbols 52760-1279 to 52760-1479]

## 52760-1279
designator X?, comment MOLEX Connector SD-52760-**79   Source: 52760-1079_sd molex.pdf
footprint 52760-1279
part A pins: 1 S
part B pins: 2 S
part C pins: 3 S
part D pins: 4 S
part E pins: 5 S
part F pins: 6 S
part G pins: 7 S
part H pins: 8 S
part I pins: 9 S
part J pins: 10 S
part K pins: 11 S
part L pins: 12 S
part M pins: 13 S
part N pins: 14 S
part O pins: 15 S
part P pins: 16 S
part Q pins: 17 S
part R pins: 18 S
part S pins: 19 S
part T pins: 20 S
part U pins: 21 S
part V pins: 22 S
part W pins: 23 S
part X pins: 24 S
part Y pins: 25 S
part Z pins: 26 S
part 27 pins: 27 S
part 28 pins: 28 S
part 29 pins: 29 S
part 30 pins: 30 S
part 31 pins: 31 S
part 32 pins: 32 S
part 33 pins: 33 S
part 34 pins: 34 S
part 35 pins: 35 S
part 36 pins: 36 S
part 37 pins: 37 S
part 38 pins: 38 S
part 39 pins: 39 S
part 40 pins: 40 S
part 41 pins: 41 S
part 42 pins: 42 S
part 43 pins: 43 S
part 44 pins: 44 S
part 45 pins: 45 S
part 46 pins: 46 S
part 47 pins: 47 S
part 48 pins: 48 S
part 49 pins: 49 S
part 50 pins: 50 S
part 51 pins: 51 S
part 52 pins: 52 S
part 53 pins: 53 S
part 54 pins: 54 S
part 55 pins: 55 S
part 56 pins: 56 S
part 57 pins: 57 S
part 58 pins: 58 S
part 59 pins: 59 S
part 60 pins: 60 S
part 61 pins: 61 S
part 62 pins: 62 S
part 63 pins: 63 S
part 64 pins: 64 S
part 65 pins: 65 S
part 66 pins: 66 S
part 67 pins: 67 S
part 68 pins: 68 S
part 69 pins: 69 S
part 70 pins: 70 S
part 71 pins: 71 S
part 72 pins: 72 S
part 73 pins: 73 S
part 74 pins: 74 S
part 75 pins: 75 S
part 76 pins: 76 S
part 77 pins: 77 S
part 78 pins: 78 S
part 79 pins: 79 S
part 80 pins: 80 S
part 81 pins: 81 S
part 82 pins: 82 S
part 83 pins: 83 S
part 84 pins: 84 S
part 85 pins: 85 S
part 86 pins: 86 S
part 87 pins: 87 S
part 88 pins: 88 S
part 89 pins: 89 S
part 90 pins: 90 S
part 91 pins: 91 S
part 92 pins: 92 S
part 93 pins: 93 S
part 94 pins: 94 S
part 95 pins: 95 S
part 96 pins: 96 S
part 97 pins: 97 S
part 98 pins: 98 S
part 99 pins: 99 S
part 100 pins: 100 S
part 101 pins: 101 S
part 102 pins: 102 S
part 103 pins: 103 S
part 104 pins: 104 S
part 105 pins: 105 S
part 106 pins: 106 S
part 107 pins: 107 S
part 108 pins: 108 S
part 109 pins: 109 S
part 110 pins: 110 S
part 111 pins: 111 S
part 112 pins: 112 S
part 113 pins: 113 S
part 114 pins: 114 S
part 115 pins: 115 S
part 116 pins: 116 S
part 117 pins: 117 S
part 118 pins: 118 S
part 119 pins: 119 S
part 120 pins: 120 S

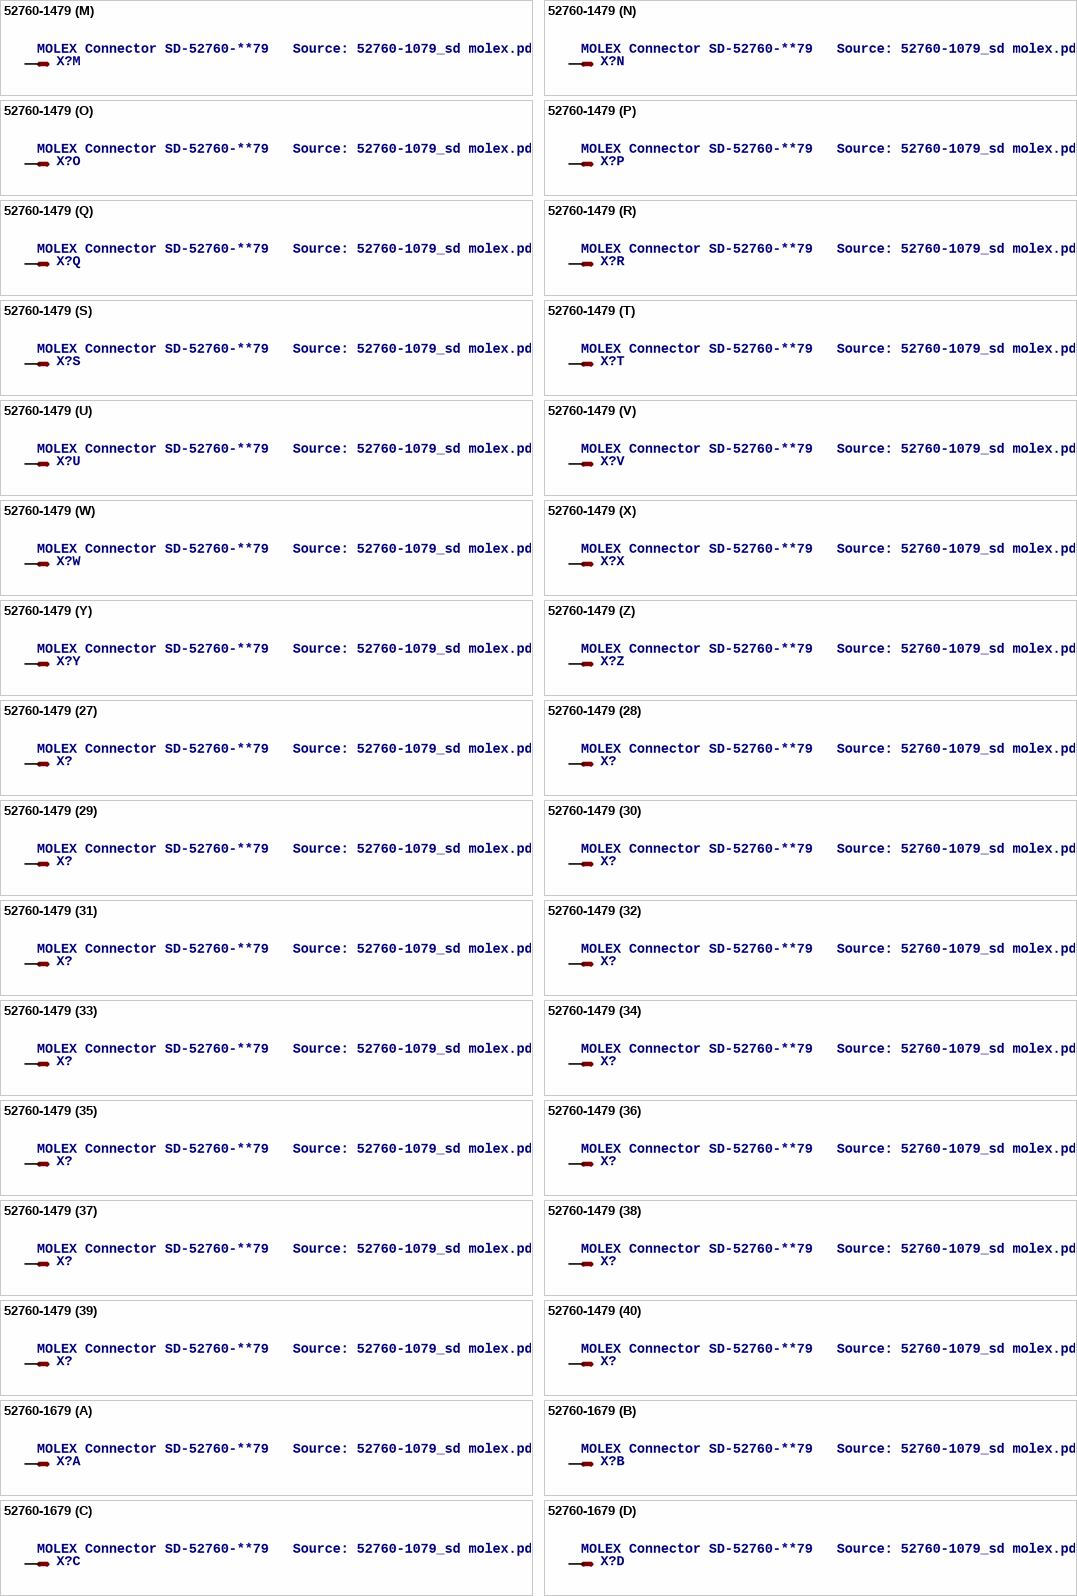
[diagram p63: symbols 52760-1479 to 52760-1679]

## 52760-1479
designator X?, comment MOLEX Connector SD-52760-**79   Source: 52760-1079_sd molex.pdf
MPN: 52760-1479
footprint 52760-1479
part A pins: 1 S
part B pins: 2 S
part C pins: 3 S
part D pins: 4 S
part E pins: 5 S
part F pins: 6 S
part G pins: 7 S
part H pins: 8 S
part I pins: 9 S
part J pins: 10 S
part K pins: 11 S
part L pins: 12 S
part M pins: 13 S
part N pins: 14 S
part O pins: 15 S
part P pins: 16 S
part Q pins: 17 S
part R pins: 18 S
part S pins: 19 S
part T pins: 20 S
part U pins: 21 S
part V pins: 22 S
part W pins: 23 S
part X pins: 24 S
part Y pins: 25 S
part Z pins: 26 S
part 27 pins: 27 S
part 28 pins: 28 S
part 29 pins: 29 S
part 30 pins: 30 S
part 31 pins: 31 S
part 32 pins: 32 S
part 33 pins: 33 S
part 34 pins: 34 S
part 35 pins: 35 S
part 36 pins: 36 S
part 37 pins: 37 S
part 38 pins: 38 S
part 39 pins: 39 S
part 40 pins: 40 S
part 41 pins: 41 S
part 42 pins: 42 S
part 43 pins: 43 S
part 44 pins: 44 S
part 45 pins: 45 S
part 46 pins: 46 S
part 47 pins: 47 S
part 48 pins: 48 S
part 49 pins: 49 S
part 50 pins: 50 S
part 51 pins: 51 S
part 52 pins: 52 S
part 53 pins: 53 S
part 54 pins: 54 S
part 55 pins: 55 S
part 56 pins: 56 S
part 57 pins: 57 S
part 58 pins: 58 S
part 59 pins: 59 S
part 60 pins: 60 S
part 61 pins: 61 S
part 62 pins: 62 S
part 63 pins: 63 S
part 64 pins: 64 S
part 65 pins: 65 S
part 66 pins: 66 S
part 67 pins: 67 S
part 68 pins: 68 S
part 69 pins: 69 S
part 70 pins: 70 S
part 71 pins: 71 S
part 72 pins: 72 S
part 73 pins: 73 S
part 74 pins: 74 S
part 75 pins: 75 S
part 76 pins: 76 S
part 77 pins: 77 S
part 78 pins: 78 S
part 79 pins: 79 S
part 80 pins: 80 S
part 81 pins: 81 S
part 82 pins: 82 S
part 83 pins: 83 S
part 84 pins: 84 S
part 85 pins: 85 S
part 86 pins: 86 S
part 87 pins: 87 S
part 88 pins: 88 S
part 89 pins: 89 S
part 90 pins: 90 S
part 91 pins: 91 S
part 92 pins: 92 S
part 93 pins: 93 S
part 94 pins: 94 S
part 95 pins: 95 S
part 96 pins: 96 S
part 97 pins: 97 S
part 98 pins: 98 S
part 99 pins: 99 S
part 100 pins: 100 S
part 101 pins: 101 S
part 102 pins: 102 S
part 103 pins: 103 S
part 104 pins: 104 S
part 105 pins: 105 S
part 106 pins: 106 S
part 107 pins: 107 S
part 108 pins: 108 S
part 109 pins: 109 S
part 110 pins: 110 S
part 111 pins: 111 S
part 112 pins: 112 S
part 113 pins: 113 S
part 114 pins: 114 S
part 115 pins: 115 S
part 116 pins: 116 S
part 117 pins: 117 S
part 118 pins: 118 S
part 119 pins: 119 S
part 120 pins: 120 S
part 121 pins: 121 S
part 122 pins: 122 S
part 123 pins: 123 S
part 124 pins: 124 S
part 125 pins: 125 S
part 126 pins: 126 S
part 127 pins: 127 S
part 128 pins: 128 S
part 129 pins: 129 S
part 130 pins: 130 S
part 131 pins: 131 S
part 132 pins: 132 S
part 133 pins: 133 S
part 134 pins: 134 S
part 135 pins: 135 S
part 136 pins: 136 S
part 137 pins: 137 S
part 138 pins: 138 S
part 139 pins: 139 S
part 140 pins: 140 S

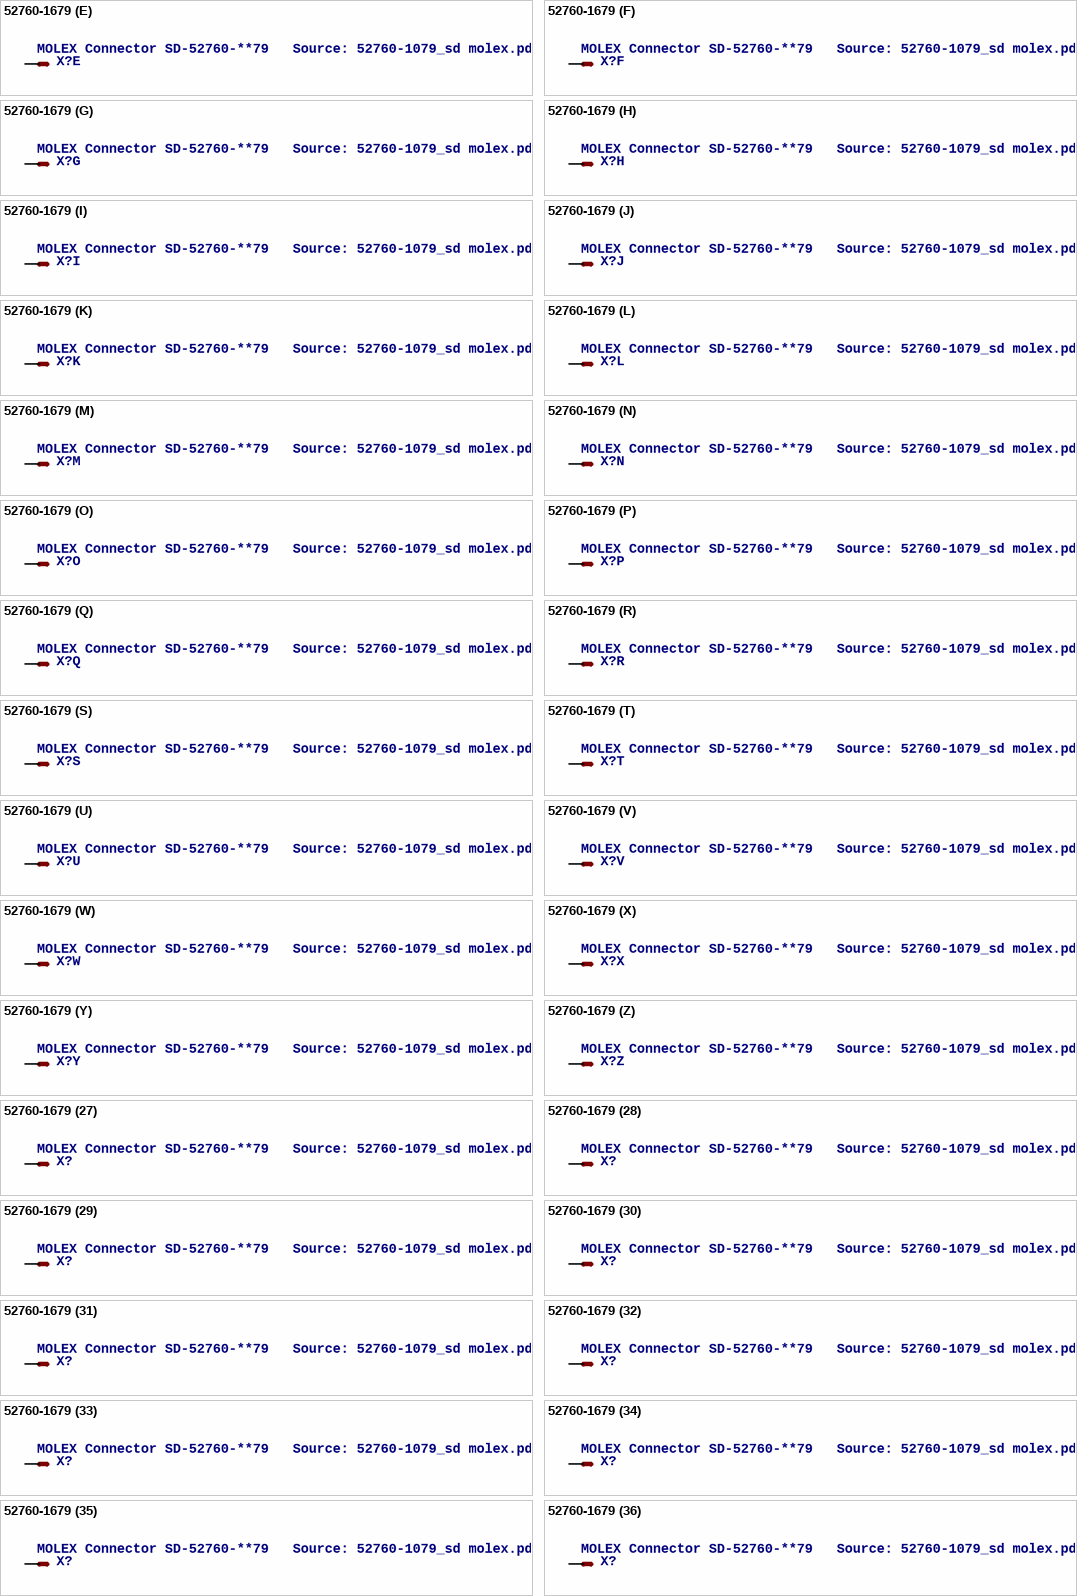
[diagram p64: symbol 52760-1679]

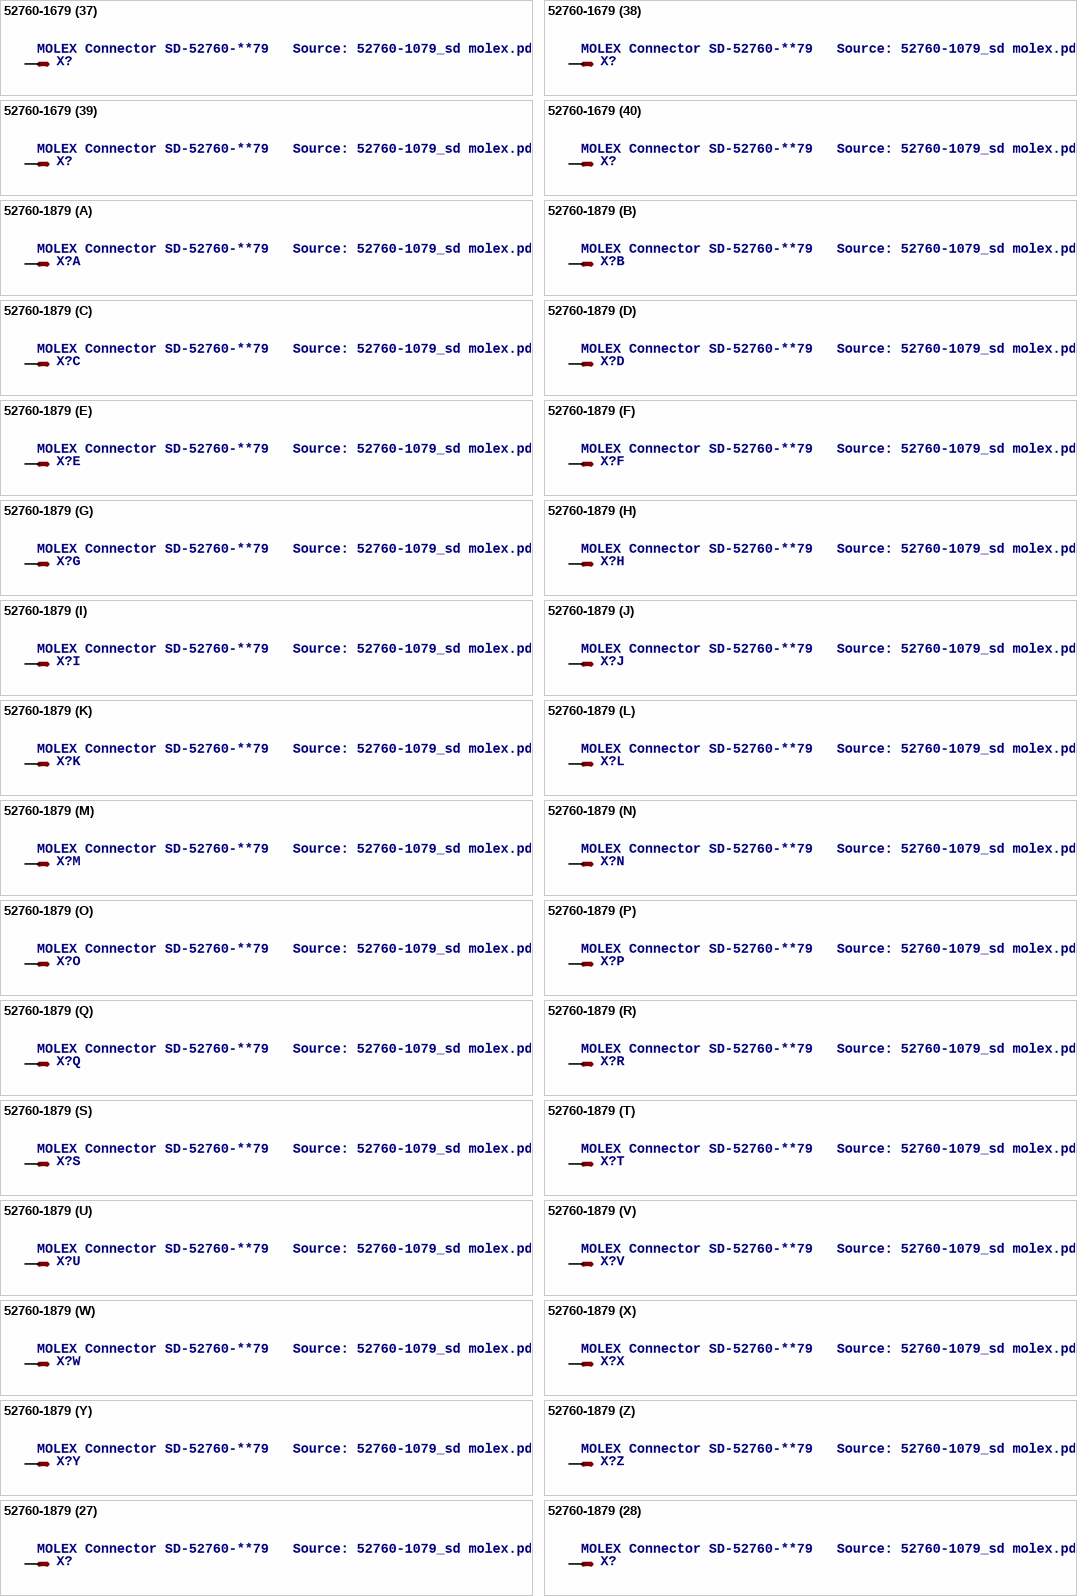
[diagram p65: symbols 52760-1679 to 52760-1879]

## 52760-1679
designator X?, comment MOLEX Connector SD-52760-**79   Source: 52760-1079_sd molex.pdf
MPN: 52760-1679
footprint 52760-1679
part A pins: 1 S
part B pins: 2 S
part C pins: 3 S
part D pins: 4 S
part E pins: 5 S
part F pins: 6 S
part G pins: 7 S
part H pins: 8 S
part I pins: 9 S
part J pins: 10 S
part K pins: 11 S
part L pins: 12 S
part M pins: 13 S
part N pins: 14 S
part O pins: 15 S
part P pins: 16 S
part Q pins: 17 S
part R pins: 18 S
part S pins: 19 S
part T pins: 20 S
part U pins: 21 S
part V pins: 22 S
part W pins: 23 S
part X pins: 24 S
part Y pins: 25 S
part Z pins: 26 S
part 27 pins: 27 S
part 28 pins: 28 S
part 29 pins: 29 S
part 30 pins: 30 S
part 31 pins: 31 S
part 32 pins: 32 S
part 33 pins: 33 S
part 34 pins: 34 S
part 35 pins: 35 S
part 36 pins: 36 S
part 37 pins: 37 S
part 38 pins: 38 S
part 39 pins: 39 S
part 40 pins: 40 S
part 41 pins: 41 S
part 42 pins: 42 S
part 43 pins: 43 S
part 44 pins: 44 S
part 45 pins: 45 S
part 46 pins: 46 S
part 47 pins: 47 S
part 48 pins: 48 S
part 49 pins: 49 S
part 50 pins: 50 S
part 51 pins: 51 S
part 52 pins: 52 S
part 53 pins: 53 S
part 54 pins: 54 S
part 55 pins: 55 S
part 56 pins: 56 S
part 57 pins: 57 S
part 58 pins: 58 S
part 59 pins: 59 S
part 60 pins: 60 S
part 61 pins: 61 S
part 62 pins: 62 S
part 63 pins: 63 S
part 64 pins: 64 S
part 65 pins: 65 S
part 66 pins: 66 S
part 67 pins: 67 S
part 68 pins: 68 S
part 69 pins: 69 S
part 70 pins: 70 S
part 71 pins: 71 S
part 72 pins: 72 S
part 73 pins: 73 S
part 74 pins: 74 S
part 75 pins: 75 S
part 76 pins: 76 S
part 77 pins: 77 S
part 78 pins: 78 S
part 79 pins: 79 S
part 80 pins: 80 S
part 81 pins: 81 S
part 82 pins: 82 S
part 83 pins: 83 S
part 84 pins: 84 S
part 85 pins: 85 S
part 86 pins: 86 S
part 87 pins: 87 S
part 88 pins: 88 S
part 89 pins: 89 S
part 90 pins: 90 S
part 91 pins: 91 S
part 92 pins: 92 S
part 93 pins: 93 S
part 94 pins: 94 S
part 95 pins: 95 S
part 96 pins: 96 S
part 97 pins: 97 S
part 98 pins: 98 S
part 99 pins: 99 S
part 100 pins: 100 S
part 101 pins: 101 S
part 102 pins: 102 S
part 103 pins: 103 S
part 104 pins: 104 S
part 105 pins: 105 S
part 106 pins: 106 S
part 107 pins: 107 S
part 108 pins: 108 S
part 109 pins: 109 S
part 110 pins: 110 S
part 111 pins: 111 S
part 112 pins: 112 S
part 113 pins: 113 S
part 114 pins: 114 S
part 115 pins: 115 S
part 116 pins: 116 S
part 117 pins: 117 S
part 118 pins: 118 S
part 119 pins: 119 S
part 120 pins: 120 S
part 121 pins: 121 S
part 122 pins: 122 S
part 123 pins: 123 S
part 124 pins: 124 S
part 125 pins: 125 S
part 126 pins: 126 S
part 127 pins: 127 S
part 128 pins: 128 S
part 129 pins: 129 S
part 130 pins: 130 S
part 131 pins: 131 S
part 132 pins: 132 S
part 133 pins: 133 S
part 134 pins: 134 S
part 135 pins: 135 S
part 136 pins: 136 S
part 137 pins: 137 S
part 138 pins: 138 S
part 139 pins: 139 S
part 140 pins: 140 S
part 141 pins: 141 S
part 142 pins: 142 S
part 143 pins: 143 S
part 144 pins: 144 S
part 145 pins: 145 S
part 146 pins: 146 S
part 147 pins: 147 S
part 148 pins: 148 S
part 149 pins: 149 S
part 150 pins: 150 S
part 151 pins: 151 S
part 152 pins: 152 S
part 153 pins: 153 S
part 154 pins: 154 S
part 155 pins: 155 S
part 156 pins: 156 S
part 157 pins: 157 S
part 158 pins: 158 S
part 159 pins: 159 S
part 160 pins: 160 S

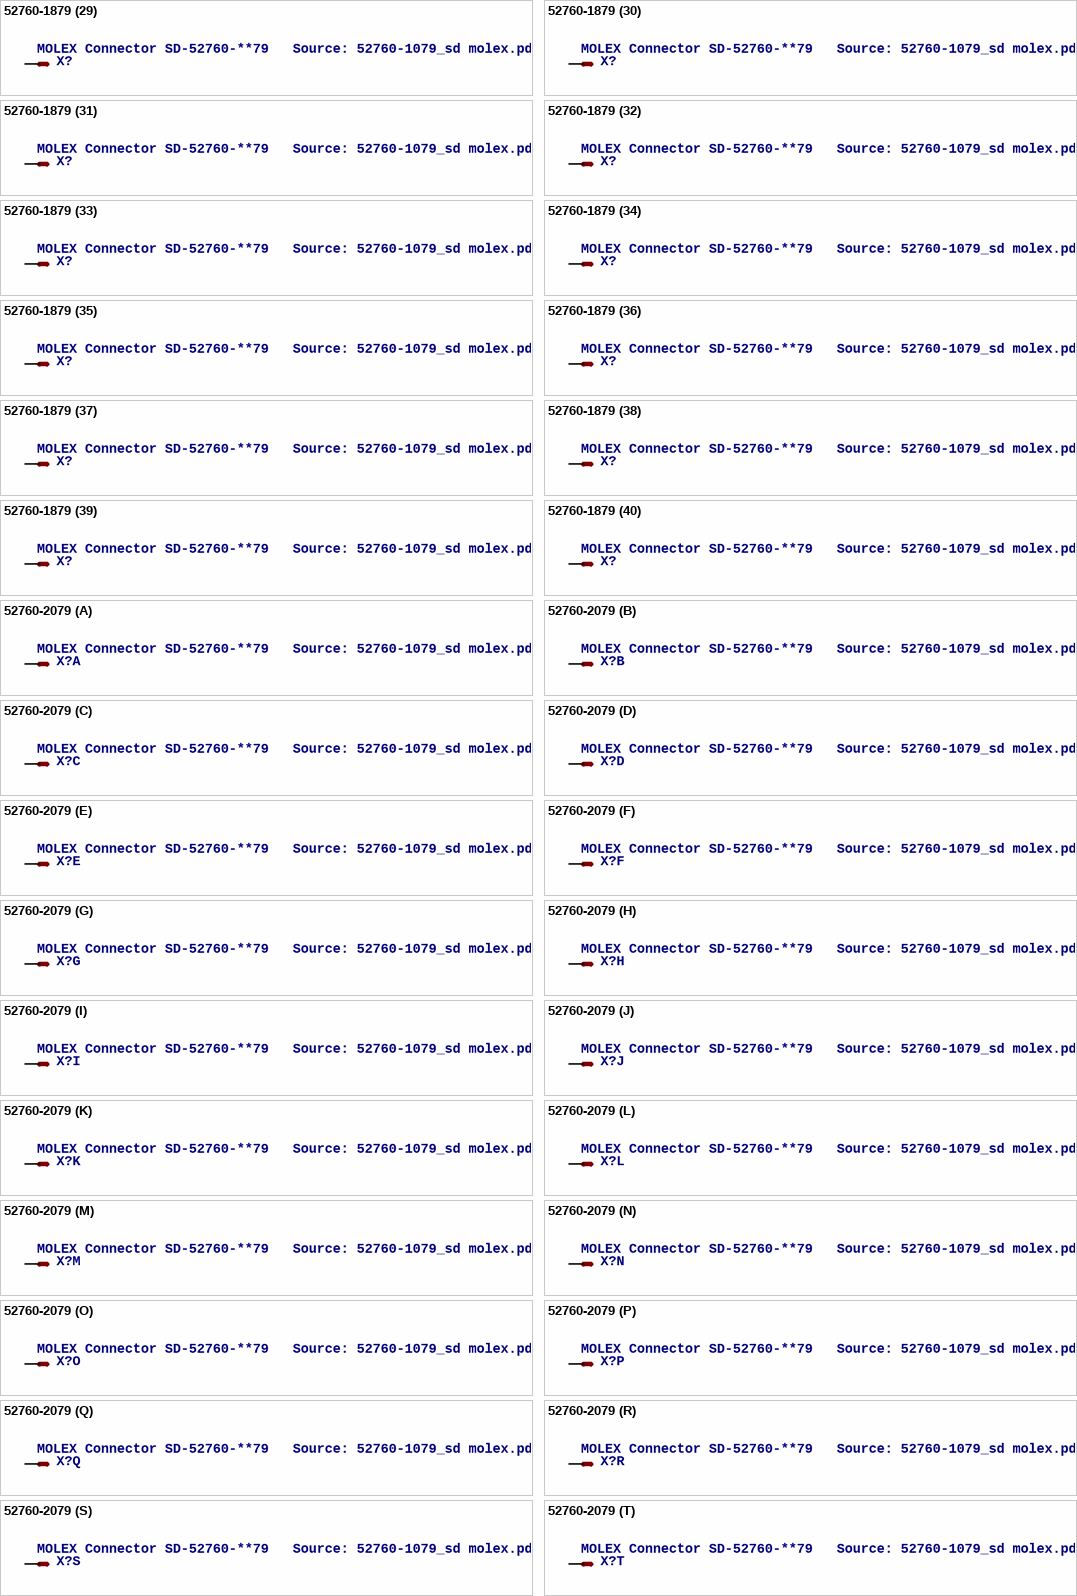
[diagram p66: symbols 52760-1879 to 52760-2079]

## 52760-1879
designator X?, comment MOLEX Connector SD-52760-**79   Source: 52760-1079_sd molex.pdf
MPN: 52760-1879
footprint 52760-1879
part A pins: 1 S
part B pins: 2 S
part C pins: 3 S
part D pins: 4 S
part E pins: 5 S
part F pins: 6 S
part G pins: 7 S
part H pins: 8 S
part I pins: 9 S
part J pins: 10 S
part K pins: 11 S
part L pins: 12 S
part M pins: 13 S
part N pins: 14 S
part O pins: 15 S
part P pins: 16 S
part Q pins: 17 S
part R pins: 18 S
part S pins: 19 S
part T pins: 20 S
part U pins: 21 S
part V pins: 22 S
part W pins: 23 S
part X pins: 24 S
part Y pins: 25 S
part Z pins: 26 S
part 27 pins: 27 S
part 28 pins: 28 S
part 29 pins: 29 S
part 30 pins: 30 S
part 31 pins: 31 S
part 32 pins: 32 S
part 33 pins: 33 S
part 34 pins: 34 S
part 35 pins: 35 S
part 36 pins: 36 S
part 37 pins: 37 S
part 38 pins: 38 S
part 39 pins: 39 S
part 40 pins: 40 S
part 41 pins: 41 S
part 42 pins: 42 S
part 43 pins: 43 S
part 44 pins: 44 S
part 45 pins: 45 S
part 46 pins: 46 S
part 47 pins: 47 S
part 48 pins: 48 S
part 49 pins: 49 S
part 50 pins: 50 S
part 51 pins: 51 S
part 52 pins: 52 S
part 53 pins: 53 S
part 54 pins: 54 S
part 55 pins: 55 S
part 56 pins: 56 S
part 57 pins: 57 S
part 58 pins: 58 S
part 59 pins: 59 S
part 60 pins: 60 S
part 61 pins: 61 S
part 62 pins: 62 S
part 63 pins: 63 S
part 64 pins: 64 S
part 65 pins: 65 S
part 66 pins: 66 S
part 67 pins: 67 S
part 68 pins: 68 S
part 69 pins: 69 S
part 70 pins: 70 S
part 71 pins: 71 S
part 72 pins: 72 S
part 73 pins: 73 S
part 74 pins: 74 S
part 75 pins: 75 S
part 76 pins: 76 S
part 77 pins: 77 S
part 78 pins: 78 S
part 79 pins: 79 S
part 80 pins: 80 S
part 81 pins: 81 S
part 82 pins: 82 S
part 83 pins: 83 S
part 84 pins: 84 S
part 85 pins: 85 S
part 86 pins: 86 S
part 87 pins: 87 S
part 88 pins: 88 S
part 89 pins: 89 S
part 90 pins: 90 S
part 91 pins: 91 S
part 92 pins: 92 S
part 93 pins: 93 S
part 94 pins: 94 S
part 95 pins: 95 S
part 96 pins: 96 S
part 97 pins: 97 S
part 98 pins: 98 S
part 99 pins: 99 S
part 100 pins: 100 S
part 101 pins: 101 S
part 102 pins: 102 S
part 103 pins: 103 S
part 104 pins: 104 S
part 105 pins: 105 S
part 106 pins: 106 S
part 107 pins: 107 S
part 108 pins: 108 S
part 109 pins: 109 S
part 110 pins: 110 S
part 111 pins: 111 S
part 112 pins: 112 S
part 113 pins: 113 S
part 114 pins: 114 S
part 115 pins: 115 S
part 116 pins: 116 S
part 117 pins: 117 S
part 118 pins: 118 S
part 119 pins: 119 S
part 120 pins: 120 S
part 121 pins: 121 S
part 122 pins: 122 S
part 123 pins: 123 S
part 124 pins: 124 S
part 125 pins: 125 S
part 126 pins: 126 S
part 127 pins: 127 S
part 128 pins: 128 S
part 129 pins: 129 S
part 130 pins: 130 S
part 131 pins: 131 S
part 132 pins: 132 S
part 133 pins: 133 S
part 134 pins: 134 S
part 135 pins: 135 S
part 136 pins: 136 S
part 137 pins: 137 S
part 138 pins: 138 S
part 139 pins: 139 S
part 140 pins: 140 S
part 141 pins: 141 S
part 142 pins: 142 S
part 143 pins: 143 S
part 144 pins: 144 S
part 145 pins: 145 S
part 146 pins: 146 S
part 147 pins: 147 S
part 148 pins: 148 S
part 149 pins: 149 S
part 150 pins: 150 S
part 151 pins: 151 S
part 152 pins: 152 S
part 153 pins: 153 S
part 154 pins: 154 S
part 155 pins: 155 S
part 156 pins: 156 S
part 157 pins: 157 S
part 158 pins: 158 S
part 159 pins: 159 S
part 160 pins: 160 S
part 161 pins: 161 S
part 162 pins: 162 S
part 163 pins: 163 S
part 164 pins: 164 S
part 165 pins: 165 S
part 166 pins: 166 S
part 167 pins: 167 S
part 168 pins: 168 S
part 169 pins: 169 S
part 170 pins: 170 S
part 171 pins: 171 S
part 172 pins: 172 S
part 173 pins: 173 S
part 174 pins: 174 S
part 175 pins: 175 S
part 176 pins: 176 S
part 177 pins: 177 S
part 178 pins: 178 S
part 179 pins: 179 S
part 180 pins: 180 S

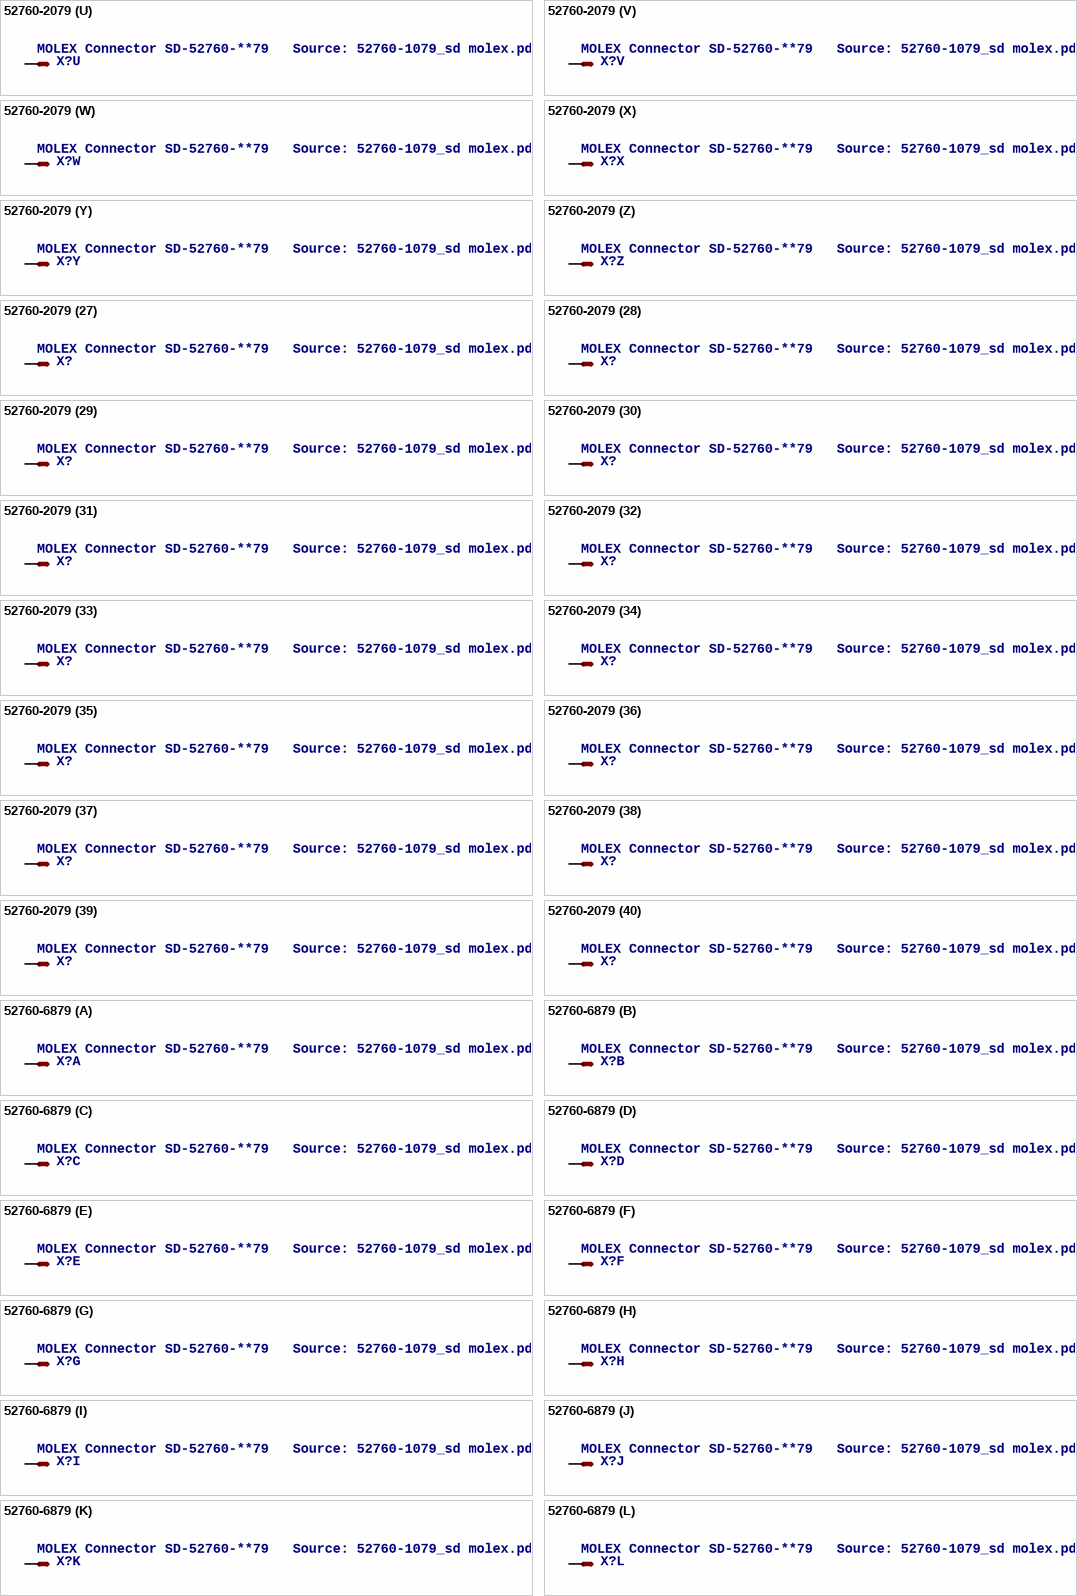
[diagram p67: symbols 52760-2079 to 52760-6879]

## 52760-2079
designator X?, comment MOLEX Connector SD-52760-**79   Source: 52760-1079_sd molex.pdf
MPN: 52760-2079
footprint 52760-2079
part A pins: 1 S
part B pins: 2 S
part C pins: 3 S
part D pins: 4 S
part E pins: 5 S
part F pins: 6 S
part G pins: 7 S
part H pins: 8 S
part I pins: 9 S
part J pins: 10 S
part K pins: 11 S
part L pins: 12 S
part M pins: 13 S
part N pins: 14 S
part O pins: 15 S
part P pins: 16 S
part Q pins: 17 S
part R pins: 18 S
part S pins: 19 S
part T pins: 20 S
part U pins: 21 S
part V pins: 22 S
part W pins: 23 S
part X pins: 24 S
part Y pins: 25 S
part Z pins: 26 S
part 27 pins: 27 S
part 28 pins: 28 S
part 29 pins: 29 S
part 30 pins: 30 S
part 31 pins: 31 S
part 32 pins: 32 S
part 33 pins: 33 S
part 34 pins: 34 S
part 35 pins: 35 S
part 36 pins: 36 S
part 37 pins: 37 S
part 38 pins: 38 S
part 39 pins: 39 S
part 40 pins: 40 S
part 41 pins: 41 S
part 42 pins: 42 S
part 43 pins: 43 S
part 44 pins: 44 S
part 45 pins: 45 S
part 46 pins: 46 S
part 47 pins: 47 S
part 48 pins: 48 S
part 49 pins: 49 S
part 50 pins: 50 S
part 51 pins: 51 S
part 52 pins: 52 S
part 53 pins: 53 S
part 54 pins: 54 S
part 55 pins: 55 S
part 56 pins: 56 S
part 57 pins: 57 S
part 58 pins: 58 S
part 59 pins: 59 S
part 60 pins: 60 S
part 61 pins: 61 S
part 62 pins: 62 S
part 63 pins: 63 S
part 64 pins: 64 S
part 65 pins: 65 S
part 66 pins: 66 S
part 67 pins: 67 S
part 68 pins: 68 S
part 69 pins: 69 S
part 70 pins: 70 S
part 71 pins: 71 S
part 72 pins: 72 S
part 73 pins: 73 S
part 74 pins: 74 S
part 75 pins: 75 S
part 76 pins: 76 S
part 77 pins: 77 S
part 78 pins: 78 S
part 79 pins: 79 S
part 80 pins: 80 S
part 81 pins: 81 S
part 82 pins: 82 S
part 83 pins: 83 S
part 84 pins: 84 S
part 85 pins: 85 S
part 86 pins: 86 S
part 87 pins: 87 S
part 88 pins: 88 S
part 89 pins: 89 S
part 90 pins: 90 S
part 91 pins: 91 S
part 92 pins: 92 S
part 93 pins: 93 S
part 94 pins: 94 S
part 95 pins: 95 S
part 96 pins: 96 S
part 97 pins: 97 S
part 98 pins: 98 S
part 99 pins: 99 S
part 100 pins: 100 S
part 101 pins: 101 S
part 102 pins: 102 S
part 103 pins: 103 S
part 104 pins: 104 S
part 105 pins: 105 S
part 106 pins: 106 S
part 107 pins: 107 S
part 108 pins: 108 S
part 109 pins: 109 S
part 110 pins: 110 S
part 111 pins: 111 S
part 112 pins: 112 S
part 113 pins: 113 S
part 114 pins: 114 S
part 115 pins: 115 S
part 116 pins: 116 S
part 117 pins: 117 S
part 118 pins: 118 S
part 119 pins: 119 S
part 120 pins: 120 S
part 121 pins: 121 S
part 122 pins: 122 S
part 123 pins: 123 S
part 124 pins: 124 S
part 125 pins: 125 S
part 126 pins: 126 S
part 127 pins: 127 S
part 128 pins: 128 S
part 129 pins: 129 S
part 130 pins: 130 S
part 131 pins: 131 S
part 132 pins: 132 S
part 133 pins: 133 S
part 134 pins: 134 S
part 135 pins: 135 S
part 136 pins: 136 S
part 137 pins: 137 S
part 138 pins: 138 S
part 139 pins: 139 S
part 140 pins: 140 S
part 141 pins: 141 S
part 142 pins: 142 S
part 143 pins: 143 S
part 144 pins: 144 S
part 145 pins: 145 S
part 146 pins: 146 S
part 147 pins: 147 S
part 148 pins: 148 S
part 149 pins: 149 S
part 150 pins: 150 S
part 151 pins: 151 S
part 152 pins: 152 S
part 153 pins: 153 S
part 154 pins: 154 S
part 155 pins: 155 S
part 156 pins: 156 S
part 157 pins: 157 S
part 158 pins: 158 S
part 159 pins: 159 S
part 160 pins: 160 S
part 161 pins: 161 S
part 162 pins: 162 S
part 163 pins: 163 S
part 164 pins: 164 S
part 165 pins: 165 S
part 166 pins: 166 S
part 167 pins: 167 S
part 168 pins: 168 S
part 169 pins: 169 S
part 170 pins: 170 S
part 171 pins: 171 S
part 172 pins: 172 S
part 173 pins: 173 S
part 174 pins: 174 S
part 175 pins: 175 S
part 176 pins: 176 S
part 177 pins: 177 S
part 178 pins: 178 S
part 179 pins: 179 S
part 180 pins: 180 S
part 181 pins: 181 S
part 182 pins: 182 S
part 183 pins: 183 S
part 184 pins: 184 S
part 185 pins: 185 S
part 186 pins: 186 S
part 187 pins: 187 S
part 188 pins: 188 S
part 189 pins: 189 S
part 190 pins: 190 S
part 191 pins: 191 S
part 192 pins: 192 S
part 193 pins: 193 S
part 194 pins: 194 S
part 195 pins: 195 S
part 196 pins: 196 S
part 197 pins: 197 S
part 198 pins: 198 S
part 199 pins: 199 S
part 200 pins: 200 S

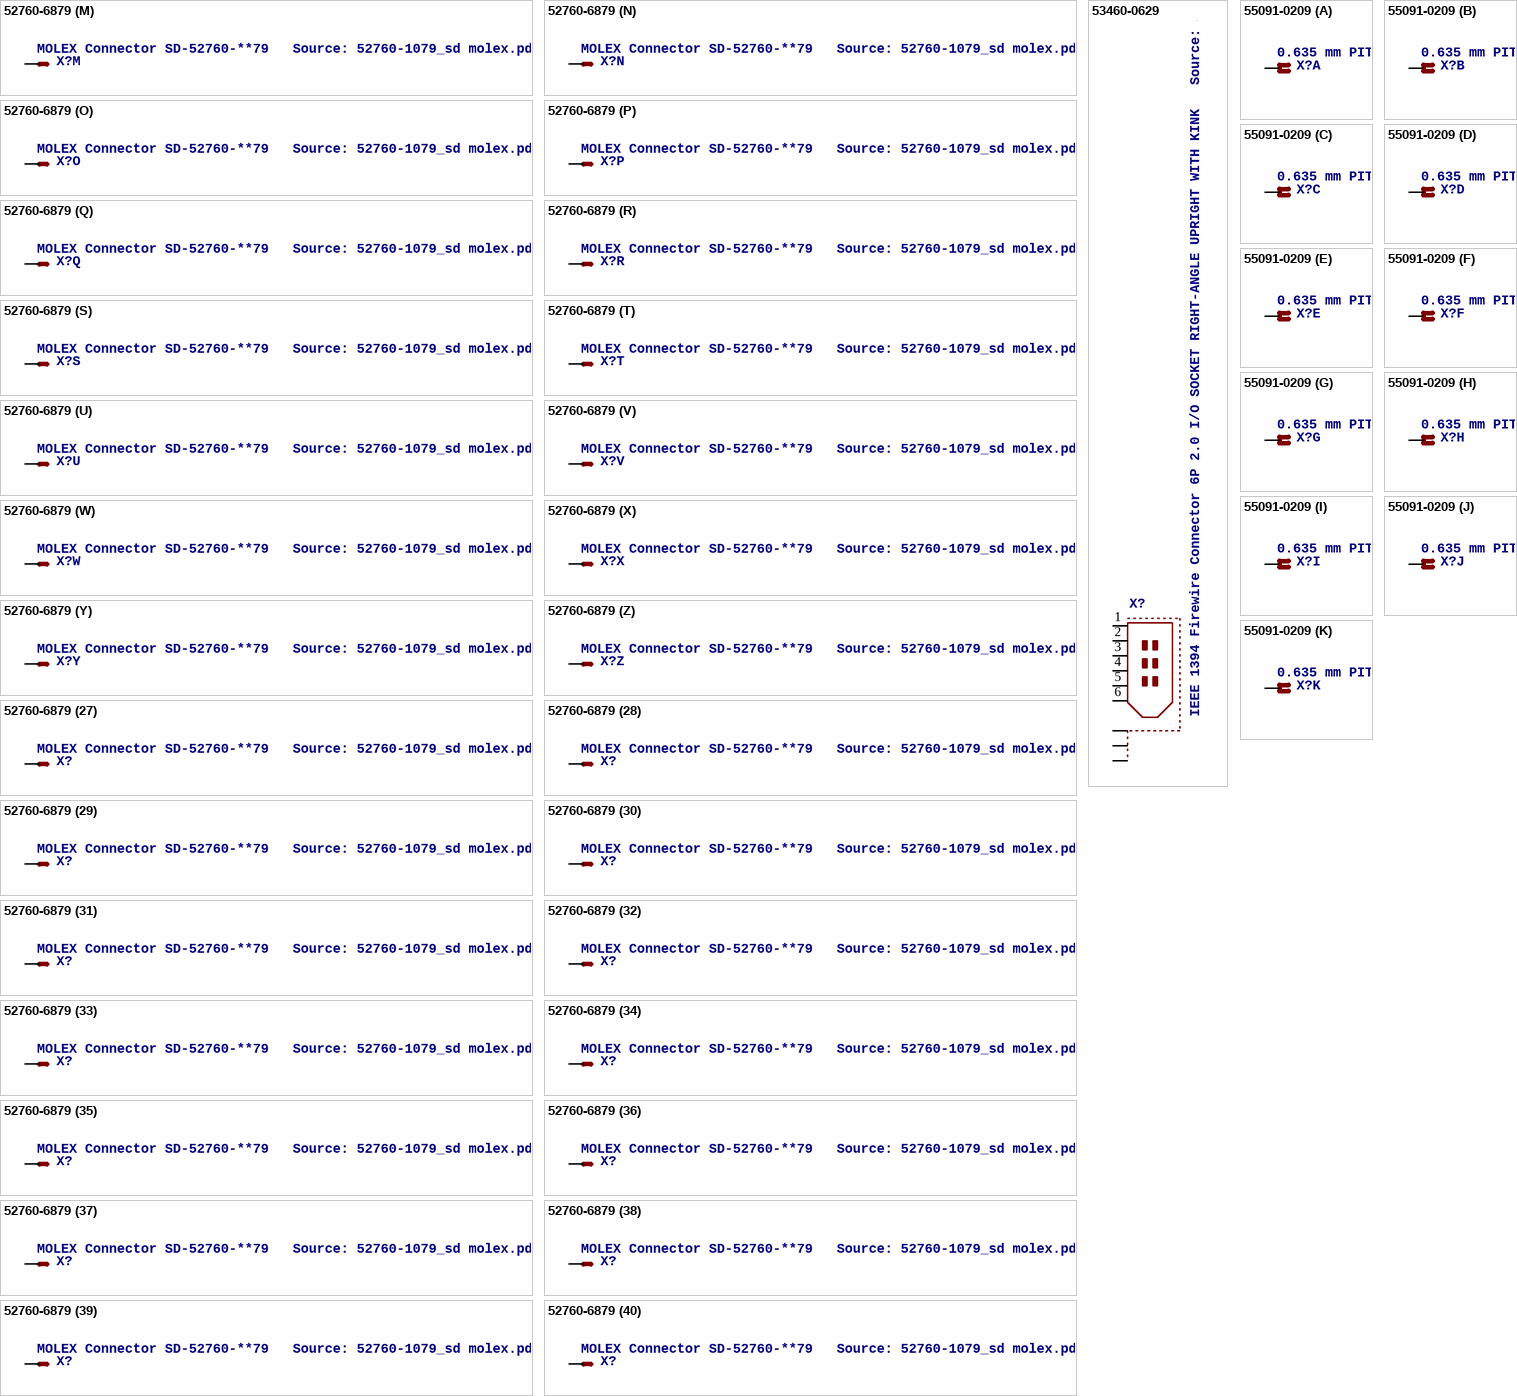
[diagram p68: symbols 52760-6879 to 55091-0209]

## 52760-6879
designator X?, comment MOLEX Connector SD-52760-**79   Source: 52760-1079_sd molex.pdf
footprint 52760-6879
part A pins: 1 S
part B pins: 2 S
part C pins: 3 S
part D pins: 4 S
part E pins: 5 S
part F pins: 6 S
part G pins: 7 S
part H pins: 8 S
part I pins: 9 S
part J pins: 10 S
part K pins: 11 S
part L pins: 12 S
part M pins: 13 S
part N pins: 14 S
part O pins: 15 S
part P pins: 16 S
part Q pins: 17 S
part R pins: 18 S
part S pins: 19 S
part T pins: 20 S
part U pins: 21 S
part V pins: 22 S
part W pins: 23 S
part X pins: 24 S
part Y pins: 25 S
part Z pins: 26 S
part 27 pins: 27 S
part 28 pins: 28 S
part 29 pins: 29 S
part 30 pins: 30 S
part 31 pins: 31 S
part 32 pins: 32 S
part 33 pins: 33 S
part 34 pins: 34 S
part 35 pins: 35 S
part 36 pins: 36 S
part 37 pins: 37 S
part 38 pins: 38 S
part 39 pins: 39 S
part 40 pins: 40 S
part 41 pins: 41 S
part 42 pins: 42 S
part 43 pins: 43 S
part 44 pins: 44 S
part 45 pins: 45 S
part 46 pins: 46 S
part 47 pins: 47 S
part 48 pins: 48 S
part 49 pins: 49 S
part 50 pins: 50 S
part 51 pins: 51 S
part 52 pins: 52 S
part 53 pins: 53 S
part 54 pins: 54 S
part 55 pins: 55 S
part 56 pins: 56 S
part 57 pins: 57 S
part 58 pins: 58 S
part 59 pins: 59 S
part 60 pins: 60 S
part 61 pins: 61 S
part 62 pins: 62 S
part 63 pins: 63 S
part 64 pins: 64 S
part 65 pins: 65 S
part 66 pins: 66 S
part 67 pins: 67 S
part 68 pins: 68 S

## 53460-0629
designator X?, comment IEEE 1394 Firewire Connector 6P 2.0 I/O SOCKET RIGHT-ANGLE UPRIGHT WITH KINK   Source: 53460-0629.pdf also DWG.NO. SD-53460-0621
MF: MOLEX
footprint 53460-0629
pins: 1, 2, 3, 4, 5, 6, S1, S2, S3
